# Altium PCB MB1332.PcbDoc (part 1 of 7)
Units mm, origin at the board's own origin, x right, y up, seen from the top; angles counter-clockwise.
Board outline 161 x 75 mm, 6 copper layers (Top Layer, Signal Layer 1, Signal Layer 2, Signal Layer 3, Signal Layer 4, Bottom Layer), stack 1.57 mm thick; 387 components, 358 nets, 1659 pads, 1180 vias.
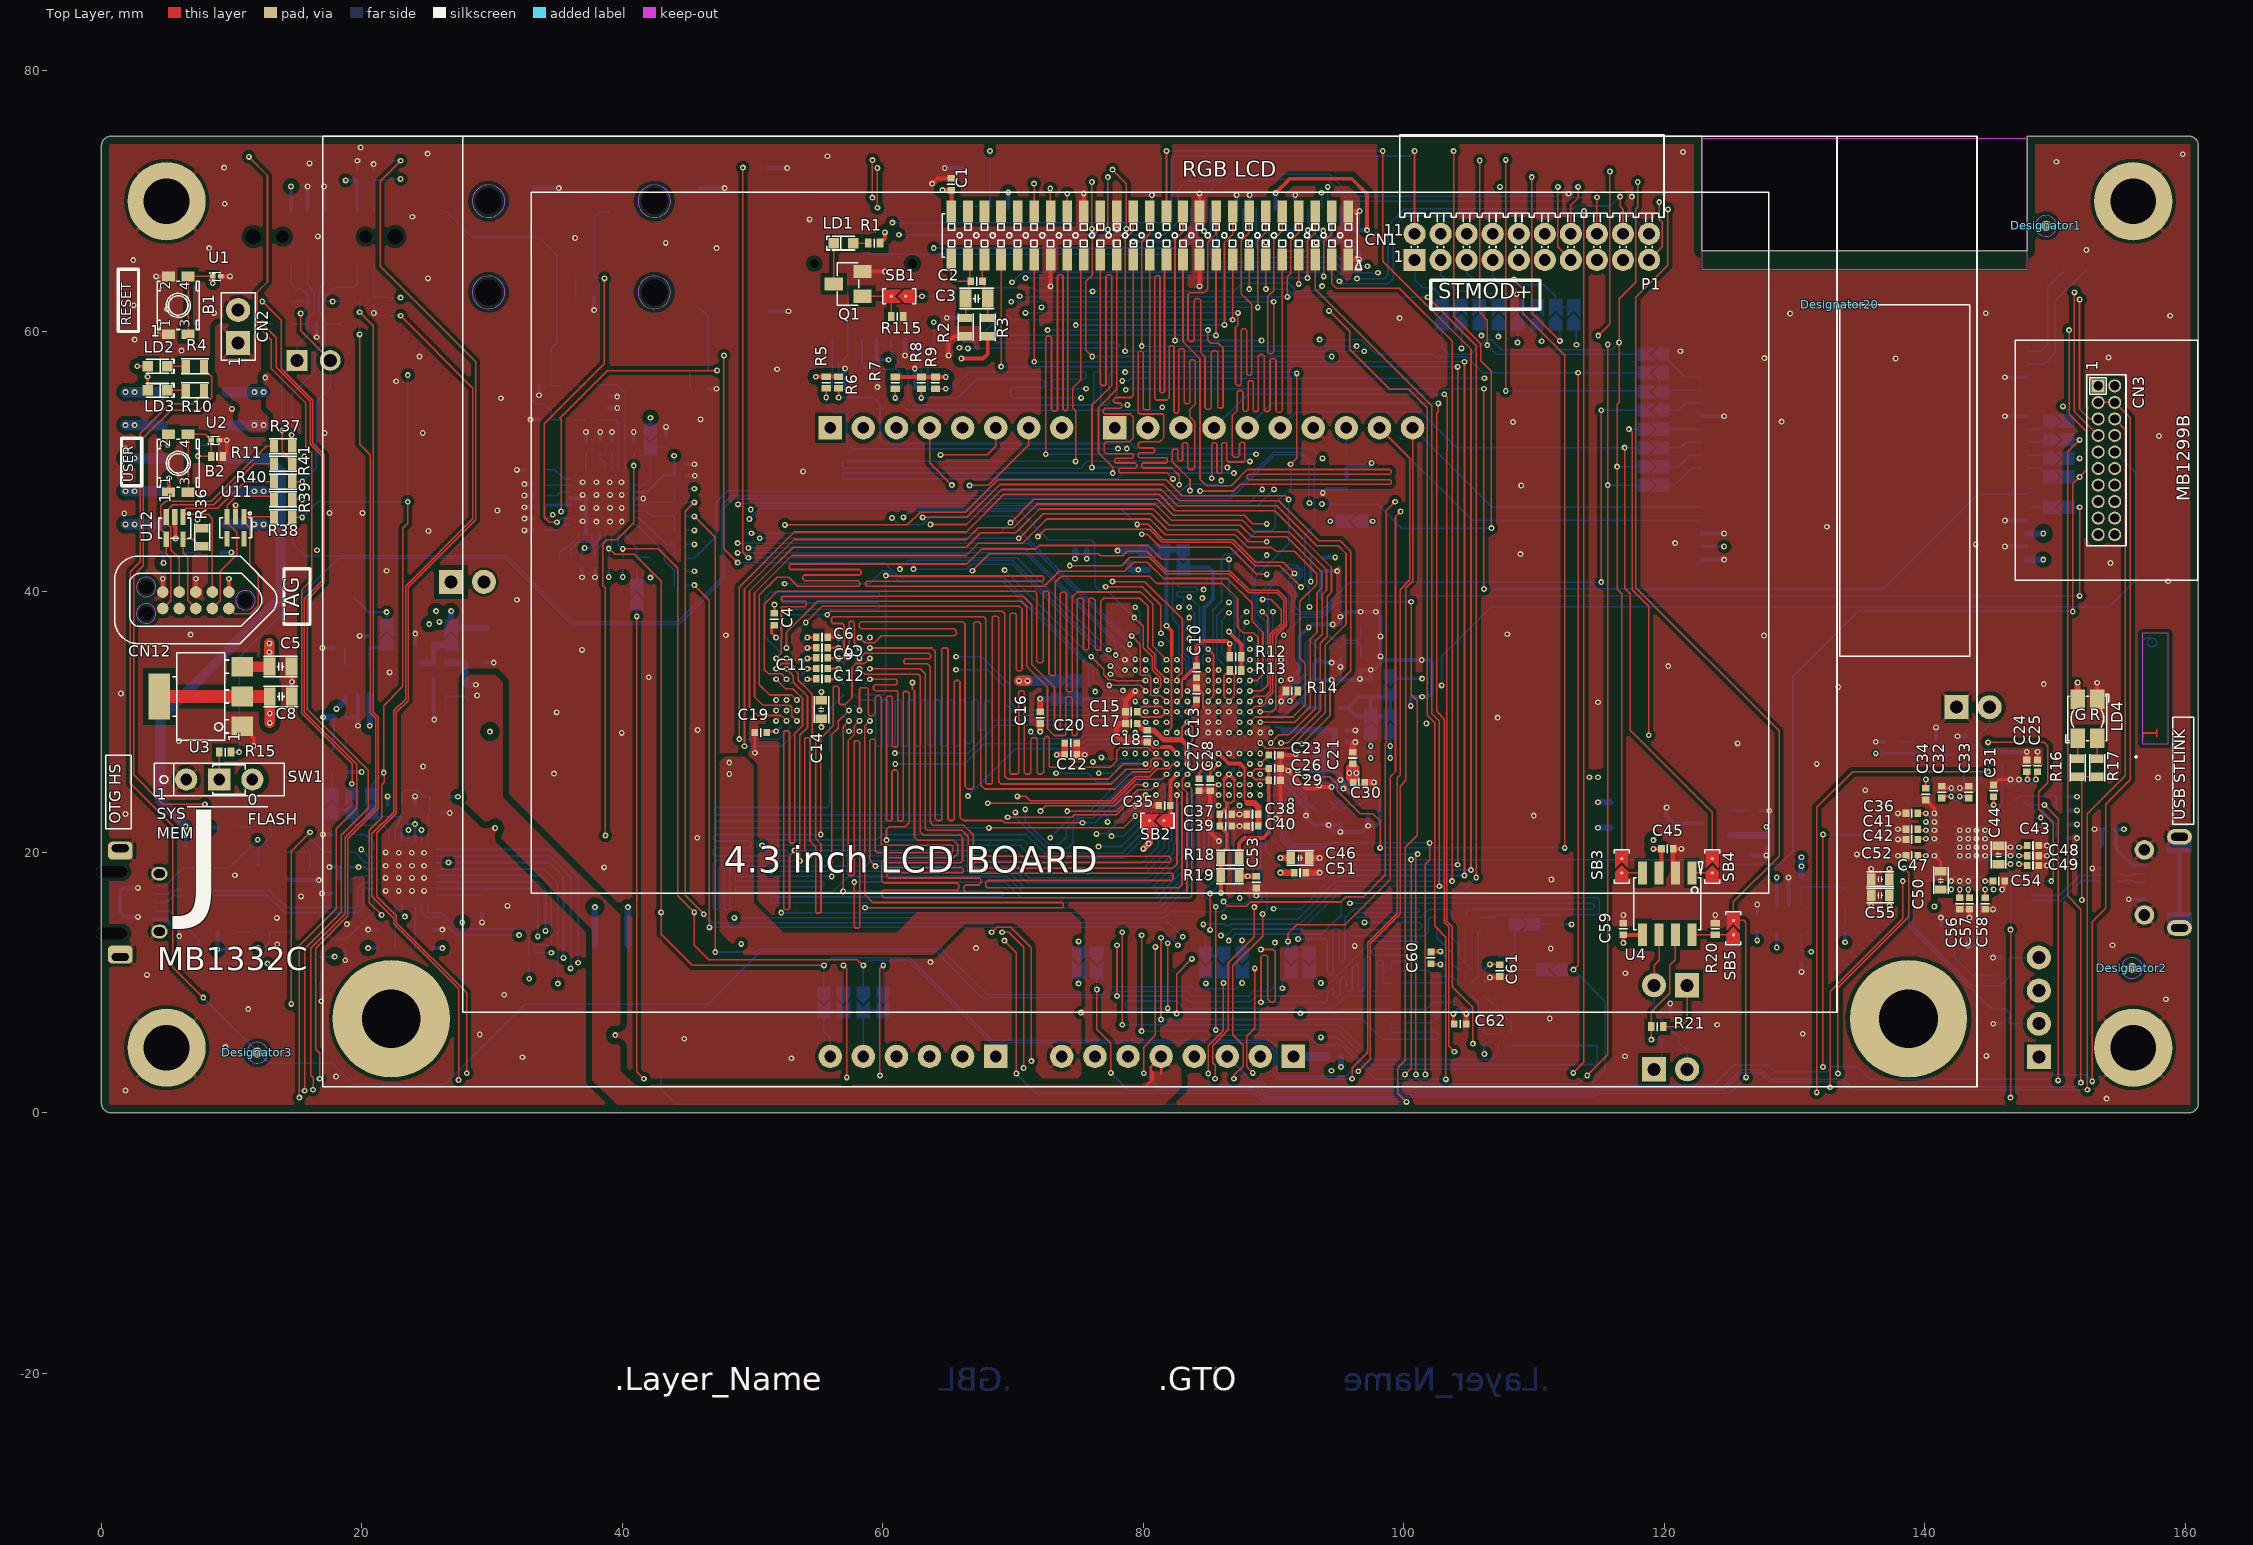
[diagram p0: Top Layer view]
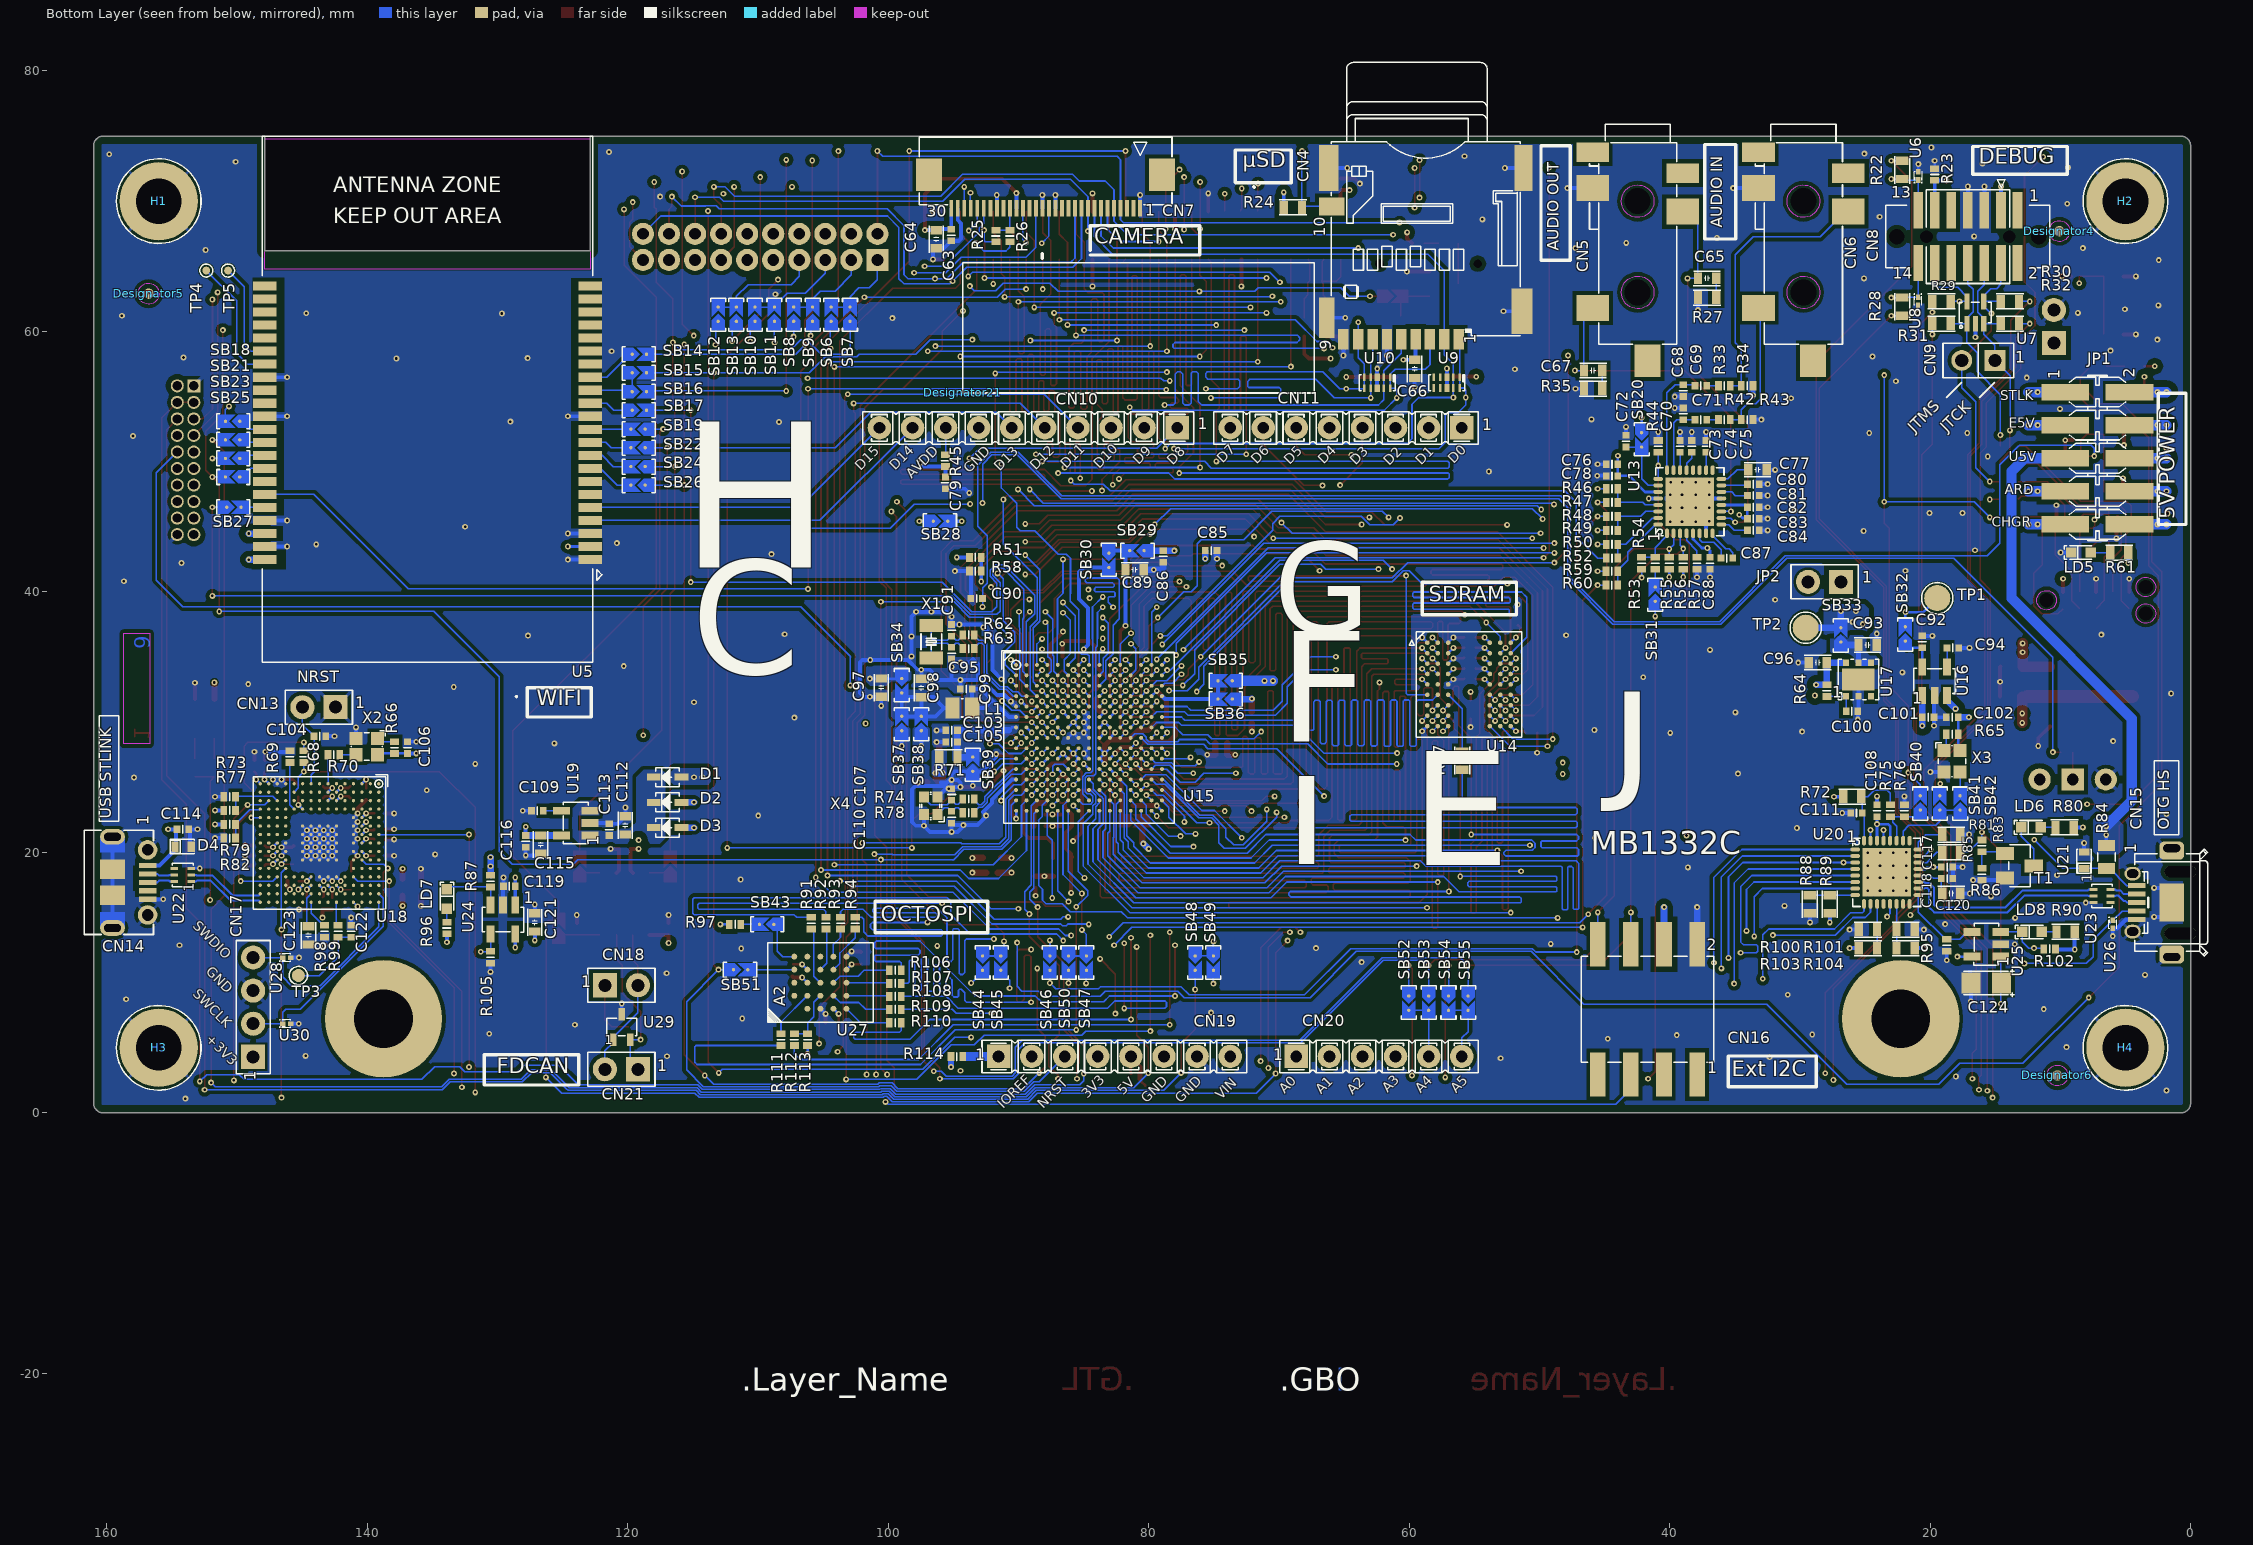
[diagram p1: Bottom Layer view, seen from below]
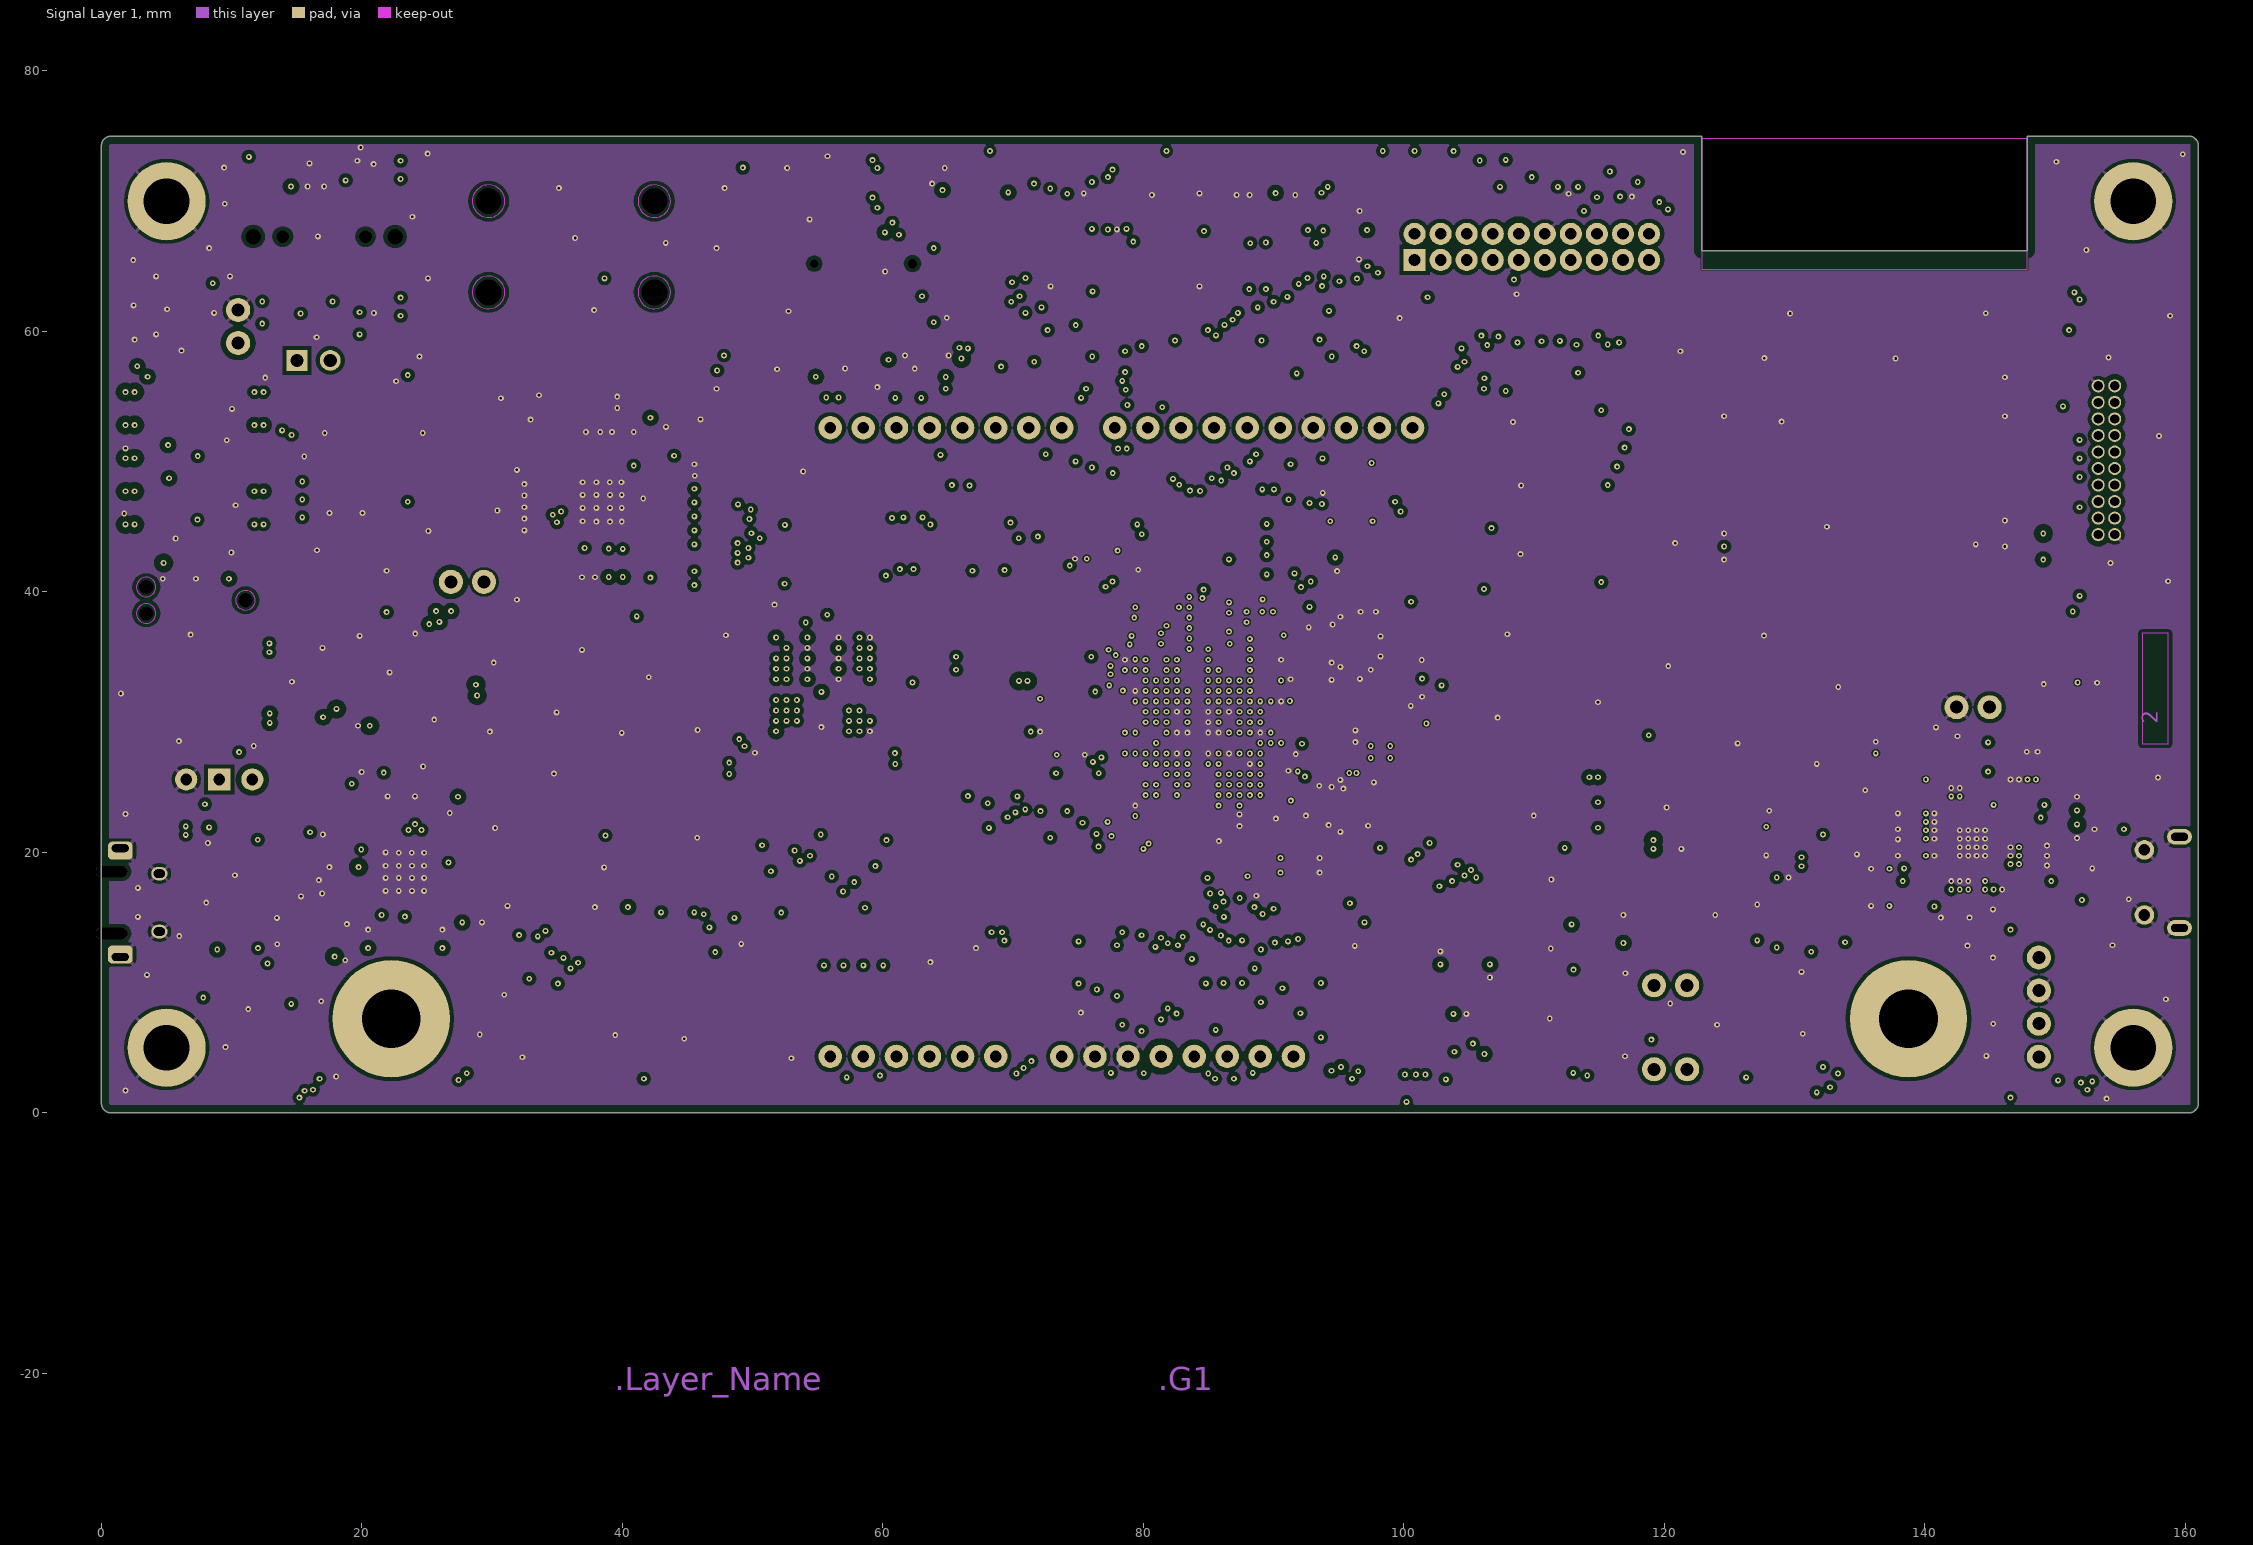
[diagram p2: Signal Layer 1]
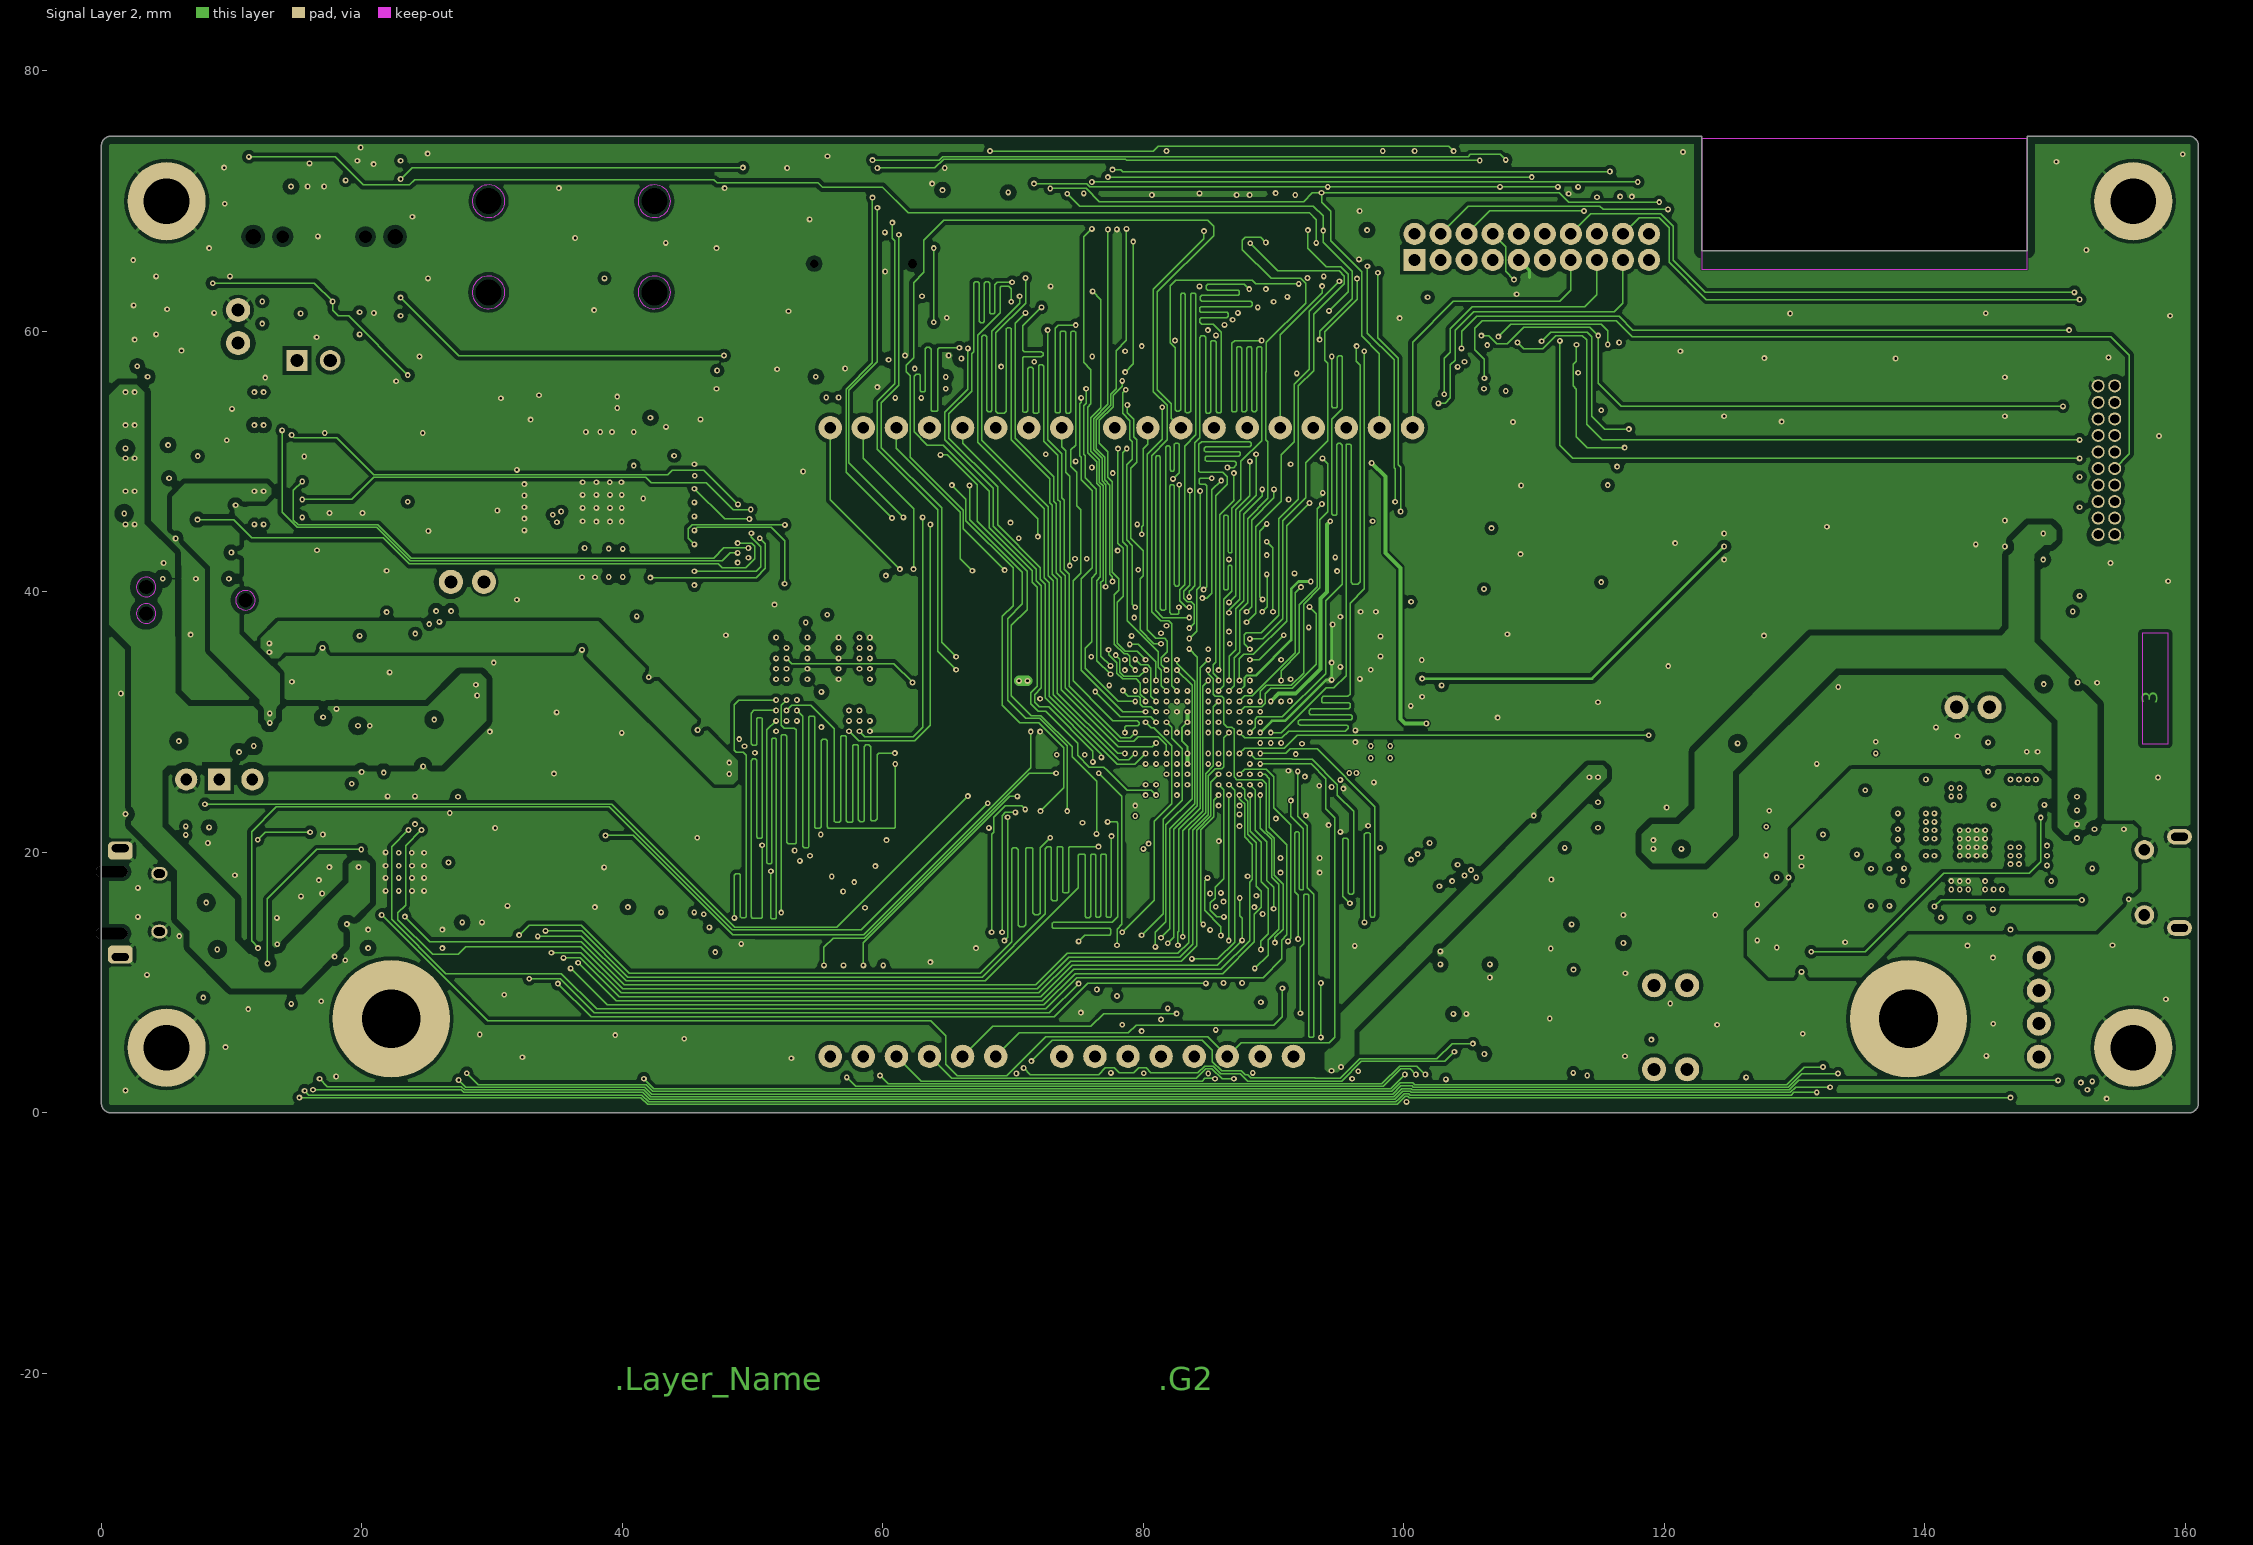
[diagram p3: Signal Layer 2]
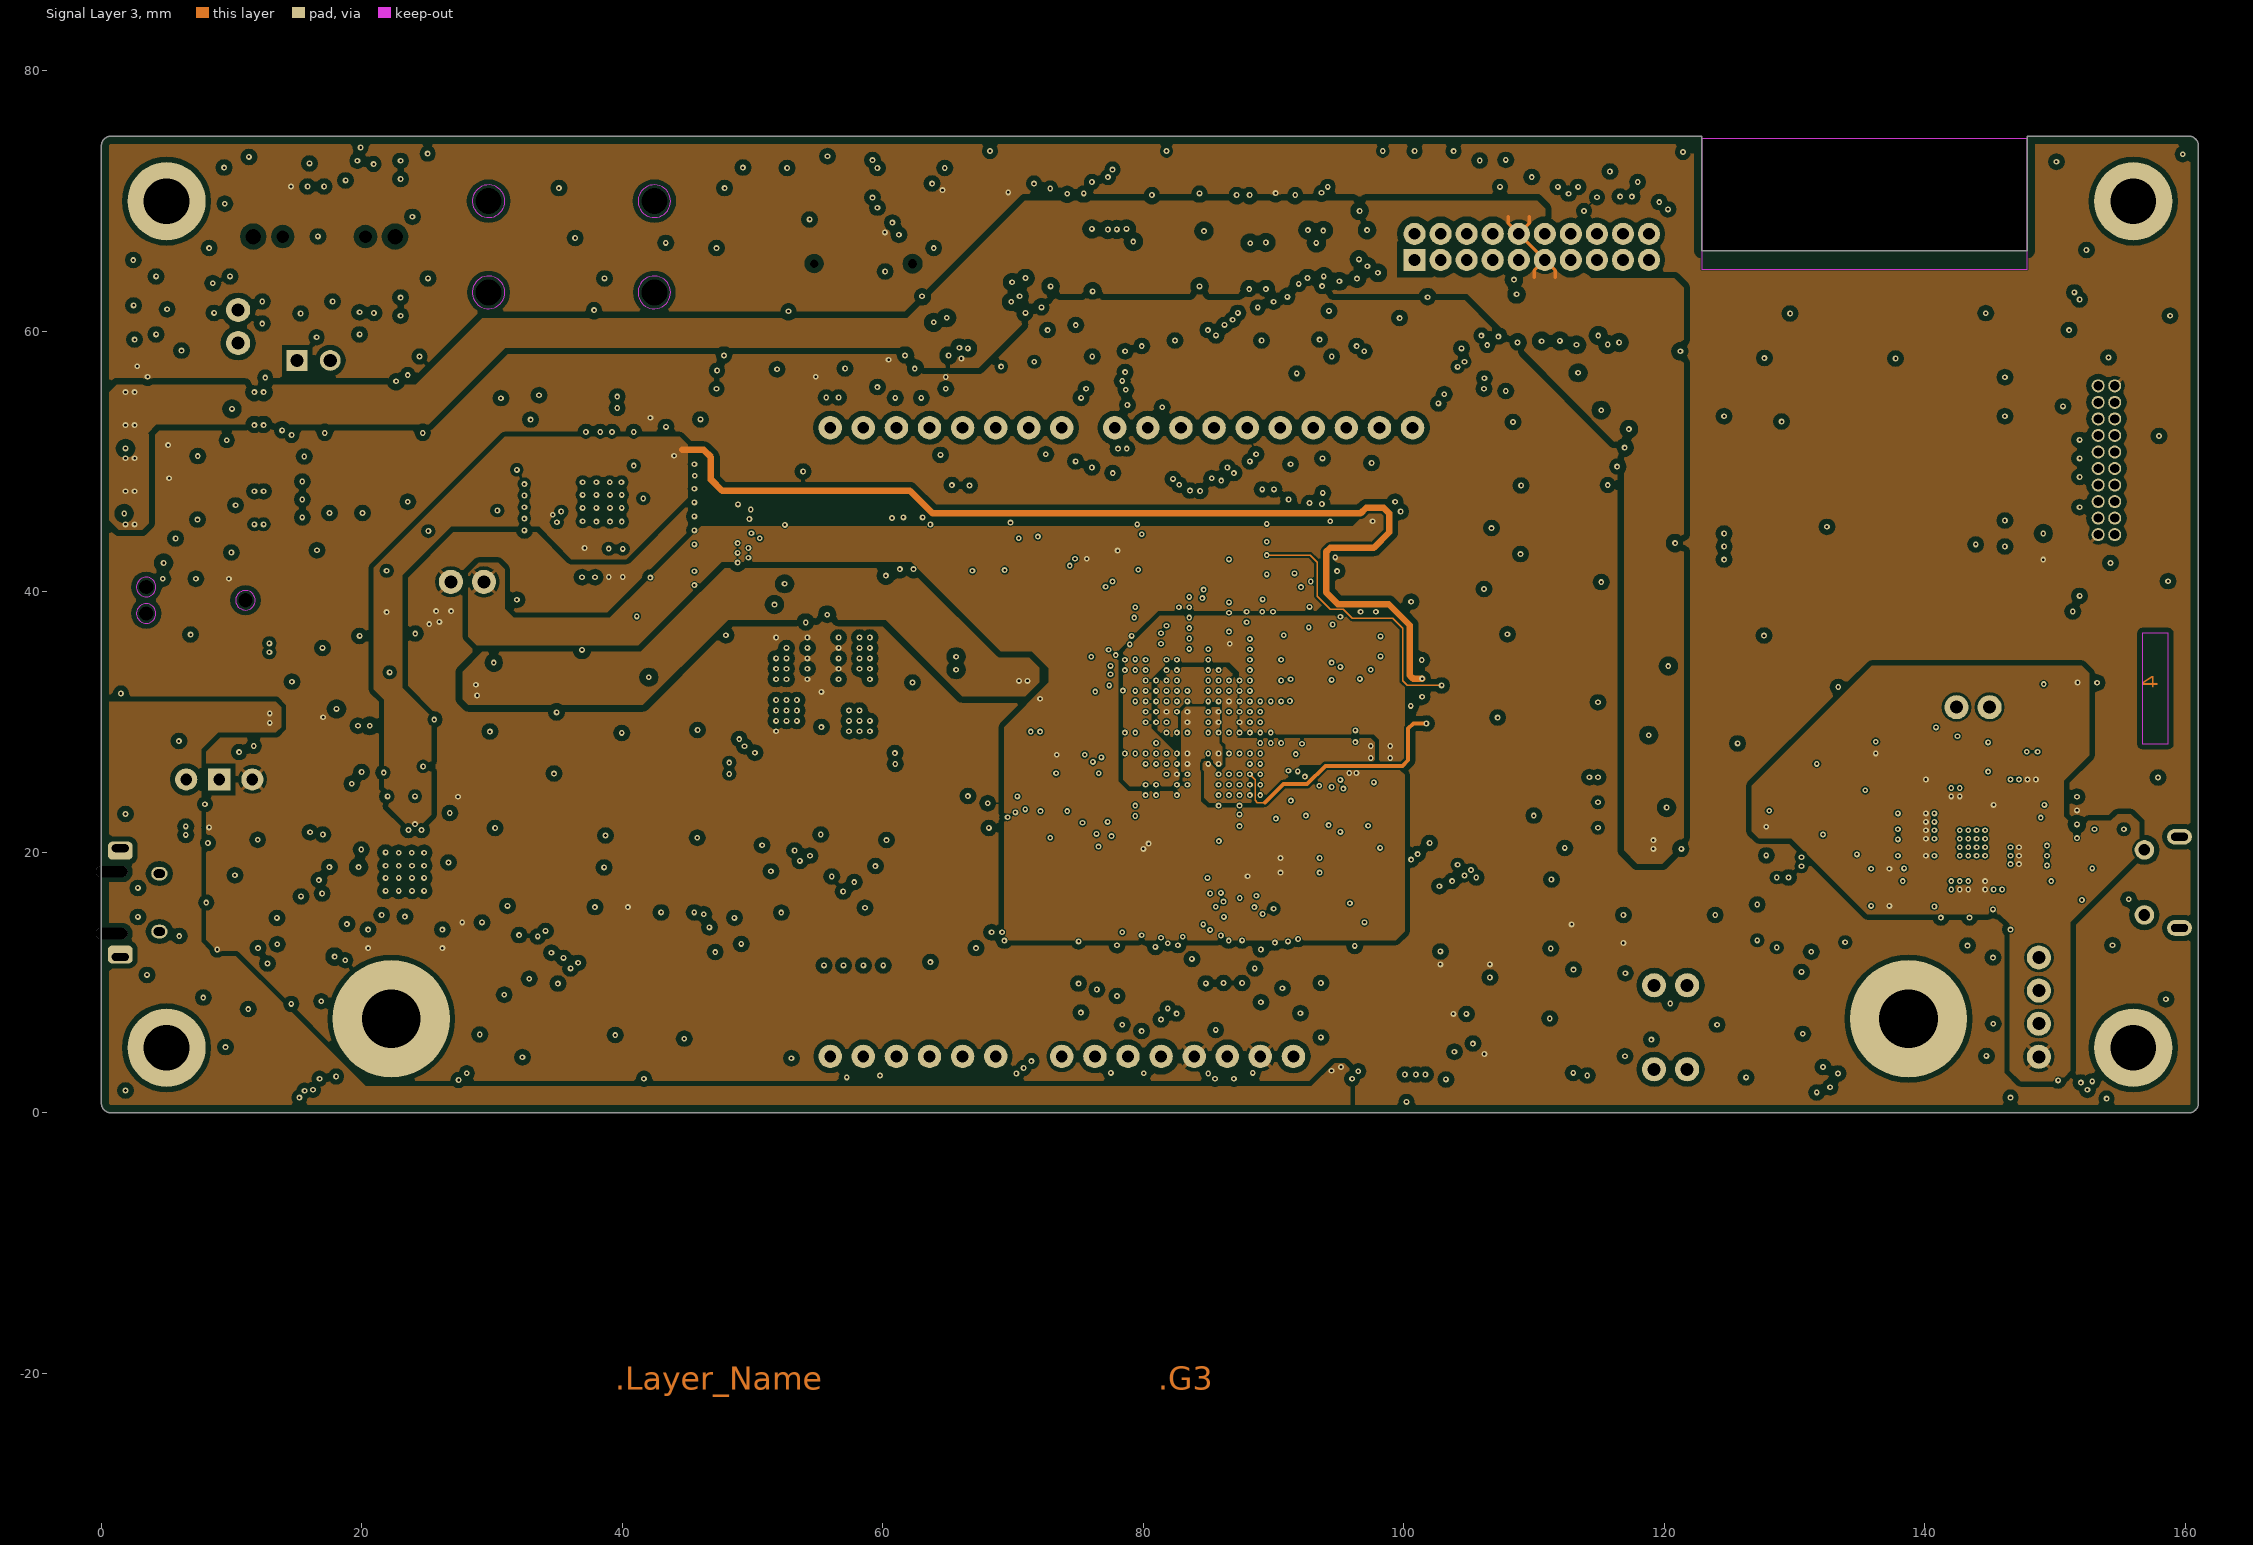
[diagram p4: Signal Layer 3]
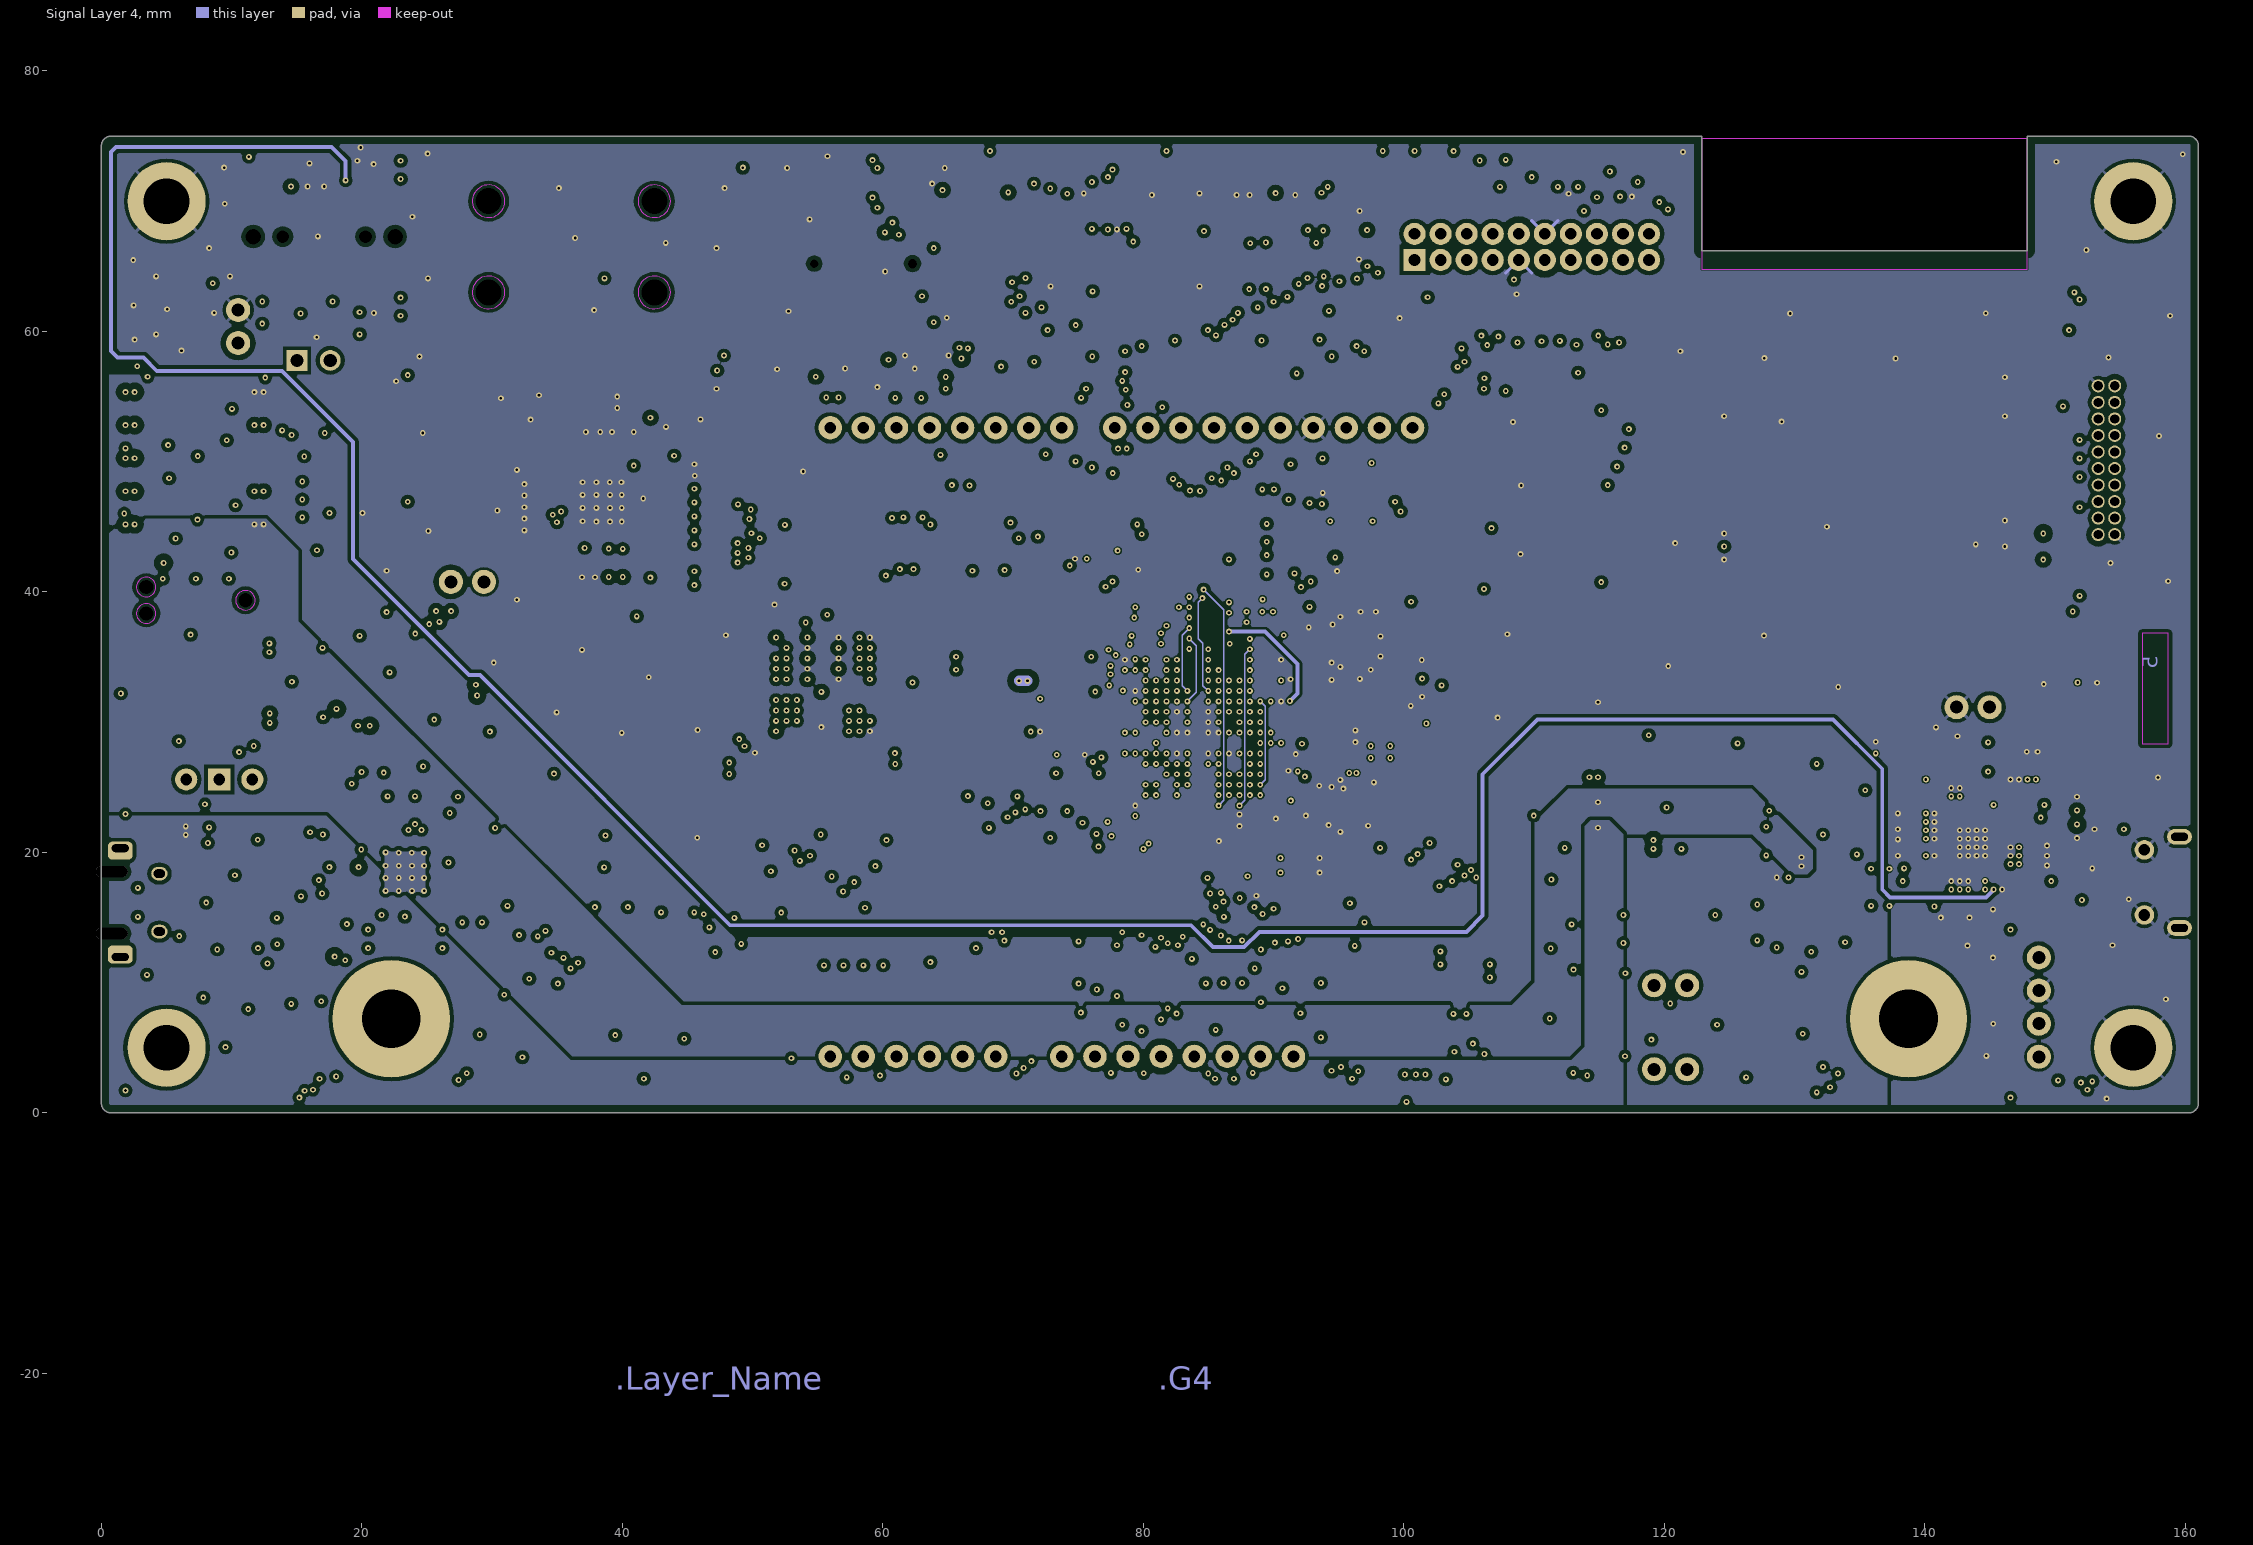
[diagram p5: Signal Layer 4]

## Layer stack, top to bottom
Top Solder: solder mask 0.015, Solder Resist, Dk 3.5
Top Layer: signal copper 0.042
Dielectric 1: prepreg 0.0991, FR-4, Dk 4.2
Signal Layer 1: signal copper 0.0348
Dielectric 2: core 0.1016, Dk 4.2
Signal Layer 2: signal copper 0.0348
Dielectric 3: prepreg 0.9457, Dk 4.2
Signal Layer 3: signal copper 0.0348
Dielectric 4: core 0.1016, Dk 4.2
Signal Layer 4: signal copper 0.0348
Dielectric 5: prepreg 0.0991, Dk 4.2
Bottom Layer: signal copper 0.042
Bottom Solder: solder mask 0.015, Solder Resist, Dk 3.5

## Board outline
0,0.75 0,74.25 cw(c0.75,74.25) 0.75,75 122.861,75 122.861,66.2 147.861,66.2 147.861,75 160.25,75 cw(c160.25,74.25) 161,74.25 161,0.75 cw(c160.25,0.75) 160.25,0 0.75,0 cw(c0.75,0.75)

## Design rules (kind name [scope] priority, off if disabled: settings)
BoardOutlineClearance [All] p1: gap=0.6 ignorepadtopadclearanceinfootprint=FALSE
Clearance Clearance_BGA-U24 [WithinRoom('RoomDefinition') And TouchesRoom('RoomDefinition')] p1: gap=0.1 ignorepadtopadclearanceinfootprint=FALSE except(0: Arc-Hole Track-Hole SMDPad-Hole THPad-Hole Via-Hole Fill-Hole Poly-Hole Region-Hole Text-Hole; 0.15: SMDPad-SMDPad; 0.2: Arc-Fill Arc-Poly Track-Fill Track-Poly SMDPad-THPad SMDPad-Fill SMDPad-Poly THPad-THPad THPad-Fill THPad-Poly Via-Via Via-Fill Fill-Poly; 0.3: Fill-Fill Poly-Poly)
Clearance Clearance_SDRAM_L1 [InNetClass('NC_SDRAM_SINGLE-55R') vs OnLayer('Top Layer')] p2: gap=0.1 ignorepadtopadclearanceinfootprint=FALSE except(0: Arc-Hole Track-Hole SMDPad-Hole THPad-Hole Via-Hole Fill-Hole Poly-Hole Region-Hole Text-Hole; 0.15: SMDPad-SMDPad; 0.2: Arc-Fill Track-Fill SMDPad-THPad SMDPad-Fill THPad-THPad THPad-Fill Via-Via Via-Fill; 0.254: Track-Track; 0.3: Arc-Poly Track-Poly SMDPad-Poly THPad-Poly Via-Poly Fill-Fill Fill-Poly Poly-Poly)
Clearance Clearance_LCD-W127 [InNetClass('NC_LCD_SINGLE-55R_W127u')] p3: gap=0.1 ignorepadtopadclearanceinfootprint=FALSE except(0: Arc-Hole Track-Hole SMDPad-Hole THPad-Hole Via-Hole Fill-Hole Poly-Hole Region-Hole Text-Hole; 0.15: SMDPad-SMDPad; 0.2: Arc-Fill Track-Fill SMDPad-THPad SMDPad-Fill THPad-THPad THPad-Fill Via-Via Via-Fill; 0.254: Track-Track; 0.3: Arc-Poly Track-Poly SMDPad-Poly THPad-Poly Via-Poly Fill-Fill Fill-Poly Poly-Poly)
Clearance Clearance_LCD_L1 [InNetClass('NC_LCD_SINGLE-55R') vs OnLayer('Top Layer')] p4: gap=0.1 ignorepadtopadclearanceinfootprint=FALSE except(0: Arc-Hole Track-Hole SMDPad-Hole THPad-Hole Via-Hole Fill-Hole Poly-Hole Region-Hole Text-Hole; 0.15: SMDPad-SMDPad; 0.2: Arc-Fill Track-Fill SMDPad-THPad SMDPad-Fill THPad-THPad THPad-Fill Via-Via Via-Fill; 0.254: Track-Track; 0.3: Arc-Poly Track-Poly SMDPad-Poly THPad-Poly Via-Poly Fill-Fill Fill-Poly Poly-Poly)
Clearance Clearance_OCTO-SPI_L1 [InNetClass('NC_OCTO-SPI_SINGLE-55R') vs OnLayer('Top Layer')] p5: gap=0.1 ignorepadtopadclearanceinfootprint=FALSE except(0: Arc-Hole Track-Hole SMDPad-Hole THPad-Hole Via-Hole Fill-Hole Poly-Hole Region-Hole Text-Hole; 0.15: SMDPad-SMDPad; 0.2: Arc-Fill Track-Fill SMDPad-THPad SMDPad-Fill THPad-THPad THPad-Fill Via-Via Via-Fill; 0.254: Track-Track; 0.3: Arc-Poly Track-Poly SMDPad-Poly THPad-Poly Via-Poly Fill-Fill Fill-Poly Poly-Poly)
Clearance Clearance_SD-CARD_L1 [InNetClass('NC_SD-CARD_SINGLE-55R') vs OnLayer('Top Layer')] p6: gap=0.1 ignorepadtopadclearanceinfootprint=FALSE except(0: Arc-Hole Track-Hole SMDPad-Hole THPad-Hole Via-Hole Fill-Hole Poly-Hole Region-Hole Text-Hole; 0.15: SMDPad-SMDPad; 0.2: Arc-Fill Track-Fill SMDPad-THPad SMDPad-Fill THPad-THPad THPad-Fill Via-Via Via-Fill; 0.254: Track-Track; 0.3: Arc-Poly Track-Poly SMDPad-Poly THPad-Poly Via-Poly Fill-Fill Fill-Poly Poly-Poly)
Clearance Clearance_CAMERA_L1 [InNetClass('NC_CAMERA_SINGLE-55R') vs OnLayer('Top Layer')] p7: gap=0.1 ignorepadtopadclearanceinfootprint=FALSE except(0: Arc-Hole Track-Hole SMDPad-Hole THPad-Hole Via-Hole Fill-Hole Poly-Hole Region-Hole Text-Hole; 0.15: SMDPad-SMDPad; 0.2: Arc-Fill Track-Fill SMDPad-THPad SMDPad-Fill THPad-THPad THPad-Fill Via-Via Via-Fill; 0.254: Track-Track; 0.3: Arc-Poly Track-Poly SMDPad-Poly THPad-Poly Via-Poly Fill-Fill Fill-Poly Poly-Poly)
Clearance Clearance_ULPI_L1 [InNetClass('NC_ULPI_SINGLE-55R') vs OnLayer('Top Layer')] p8: gap=0.1 ignorepadtopadclearanceinfootprint=FALSE except(0: Arc-Hole Track-Hole SMDPad-Hole THPad-Hole Via-Hole Fill-Hole Poly-Hole Region-Hole Text-Hole; 0.15: SMDPad-SMDPad; 0.2: Arc-Fill Track-Fill SMDPad-THPad SMDPad-Fill THPad-THPad THPad-Fill Via-Via Via-Fill; 0.254: Track-Track; 0.3: Arc-Poly Track-Poly SMDPad-Poly THPad-Poly Via-Poly Fill-Fill Fill-Poly Poly-Poly)
Clearance Clearance_SDRAM_L6 [InNetClass('NC_SDRAM_SINGLE-55R') vs OnLayer('Bottom Layer')] p9: gap=0.1 ignorepadtopadclearanceinfootprint=FALSE except(0: Arc-Hole Track-Hole SMDPad-Hole THPad-Hole Via-Hole Fill-Hole Poly-Hole Region-Hole Text-Hole; 0.15: SMDPad-SMDPad; 0.2: Arc-Fill Track-Fill SMDPad-THPad SMDPad-Fill THPad-THPad THPad-Fill Via-Via Via-Fill; 0.254: Track-Track; 0.3: Arc-Poly Track-Poly SMDPad-Poly THPad-Poly Via-Poly Fill-Fill Fill-Poly Poly-Poly)
Clearance Clearance_LCD_L6 [InNetClass('NC_LCD_SINGLE-55R') vs OnLayer('Bottom Layer')] p10: gap=0.1 ignorepadtopadclearanceinfootprint=FALSE except(0: Arc-Hole Track-Hole SMDPad-Hole THPad-Hole Via-Hole Fill-Hole Poly-Hole Region-Hole Text-Hole; 0.15: SMDPad-SMDPad; 0.2: Arc-Fill Track-Fill SMDPad-THPad SMDPad-Fill THPad-THPad THPad-Fill Via-Via Via-Fill; 0.254: Track-Track; 0.3: Arc-Poly Track-Poly SMDPad-Poly THPad-Poly Via-Poly Fill-Fill Fill-Poly Poly-Poly)
Clearance Clearance_OCTO-SPI_L6 [InNetClass('NC_OCTO-SPI_SINGLE-55R') vs OnLayer('Bottom Layer')] p11: gap=0.1 ignorepadtopadclearanceinfootprint=FALSE except(0: Arc-Hole Track-Hole SMDPad-Hole THPad-Hole Via-Hole Fill-Hole Poly-Hole Region-Hole Text-Hole; 0.15: SMDPad-SMDPad; 0.2: Arc-Fill Track-Fill SMDPad-THPad SMDPad-Fill THPad-THPad THPad-Fill Via-Via Via-Fill; 0.254: Track-Track; 0.3: Arc-Poly Track-Poly SMDPad-Poly THPad-Poly Via-Poly Fill-Fill Fill-Poly Poly-Poly)
Clearance Clearance_SD-CARD_L6 [InNetClass('NC_SD-CARD_SINGLE-55R') vs OnLayer('Bottom Layer')] p12: gap=0.1 ignorepadtopadclearanceinfootprint=FALSE except(0: Arc-Hole Track-Hole SMDPad-Hole THPad-Hole Via-Hole Fill-Hole Poly-Hole Region-Hole Text-Hole; 0.15: SMDPad-SMDPad; 0.2: Arc-Fill Track-Fill SMDPad-THPad SMDPad-Fill THPad-THPad THPad-Fill Via-Via Via-Fill; 0.254: Track-Track; 0.3: Arc-Poly Track-Poly SMDPad-Poly THPad-Poly Via-Poly Fill-Fill Fill-Poly Poly-Poly)
Clearance Clearance_CAMERA_L6 [InNetClass('NC_CAMERA_SINGLE-55R') vs OnLayer('Bottom Layer')] p13: gap=0.1 ignorepadtopadclearanceinfootprint=FALSE except(0: Arc-Hole Track-Hole SMDPad-Hole THPad-Hole Via-Hole Fill-Hole Poly-Hole Region-Hole Text-Hole; 0.15: SMDPad-SMDPad; 0.2: Arc-Fill Track-Fill SMDPad-THPad SMDPad-Fill THPad-THPad THPad-Fill Via-Via Via-Fill; 0.254: Track-Track; 0.3: Arc-Poly Track-Poly SMDPad-Poly THPad-Poly Via-Poly Fill-Fill Fill-Poly Poly-Poly)
Clearance Clearance_ULPI_L6 [InNetClass('NC_ULPI_SINGLE-55R') vs OnLayer('Bottom Layer')] p14: gap=0.1 ignorepadtopadclearanceinfootprint=FALSE except(0: Arc-Hole Track-Hole SMDPad-Hole THPad-Hole Via-Hole Fill-Hole Poly-Hole Region-Hole Text-Hole; 0.15: SMDPad-SMDPad; 0.2: Arc-Fill Track-Fill SMDPad-THPad SMDPad-Fill THPad-THPad THPad-Fill Via-Via Via-Fill; 0.254: Track-Track; 0.3: Arc-Poly Track-Poly SMDPad-Poly THPad-Poly Via-Poly Fill-Fill Fill-Poly Poly-Poly)
Clearance Clearance_SDRAM_L3 [InNetClass('NC_SDRAM_SINGLE-55R') vs OnLayer('Signal Layer 2')] p15: gap=0.1 ignorepadtopadclearanceinfootprint=FALSE except(0: Arc-Hole Track-Hole SMDPad-Hole THPad-Hole Via-Hole Fill-Hole Poly-Hole Region-Hole Text-Hole; 0.15: SMDPad-SMDPad; 0.2: Arc-Fill Track-Fill SMDPad-THPad SMDPad-Fill THPad-THPad THPad-Fill Via-Via Via-Fill; 0.204: Track-Track; 0.3: Arc-Poly Track-Poly SMDPad-Poly THPad-Poly Via-Poly Fill-Fill Fill-Poly Poly-Poly)
Clearance Clearance_LCD_L3 [InNetClass('NC_LCD_SINGLE-55R') vs OnLayer('Signal Layer 2')] p16: gap=0.1 ignorepadtopadclearanceinfootprint=FALSE except(0: Arc-Hole Track-Hole SMDPad-Hole THPad-Hole Via-Hole Fill-Hole Poly-Hole Region-Hole Text-Hole; 0.15: SMDPad-SMDPad; 0.2: Arc-Fill Track-Fill SMDPad-THPad SMDPad-Fill THPad-THPad THPad-Fill Via-Via Via-Fill; 0.204: Track-Track; 0.3: Arc-Poly Track-Poly SMDPad-Poly THPad-Poly Via-Poly Fill-Fill Fill-Poly Poly-Poly)
Clearance Clearance_OCTO-SPI_L3 [InNetClass('NC_OCTO-SPI_SINGLE-55R') vs OnLayer('Signal Layer 2')] p17: gap=0.1 ignorepadtopadclearanceinfootprint=FALSE except(0: Arc-Hole Track-Hole SMDPad-Hole THPad-Hole Via-Hole Fill-Hole Poly-Hole Region-Hole Text-Hole; 0.15: SMDPad-SMDPad; 0.2: Arc-Fill Track-Fill SMDPad-THPad SMDPad-Fill THPad-THPad THPad-Fill Via-Via Via-Fill; 0.204: Track-Track; 0.3: Arc-Poly Track-Poly SMDPad-Poly THPad-Poly Via-Poly Fill-Fill Fill-Poly Poly-Poly)
Clearance Clearance_SD-CARD_L3 [InNetClass('NC_SD-CARD_SINGLE-55R') vs OnLayer('Signal Layer 2')] p18: gap=0.1 ignorepadtopadclearanceinfootprint=FALSE except(0: Arc-Hole Track-Hole SMDPad-Hole THPad-Hole Via-Hole Fill-Hole Poly-Hole Region-Hole Text-Hole; 0.15: SMDPad-SMDPad; 0.2: Arc-Fill Track-Fill SMDPad-THPad SMDPad-Fill THPad-THPad THPad-Fill Via-Via Via-Fill; 0.204: Track-Track; 0.3: Arc-Poly Track-Poly SMDPad-Poly THPad-Poly Via-Poly Fill-Fill Fill-Poly Poly-Poly)
Clearance Clearance_CAMERA_L3 [InNetClass('NC_CAMERA_SINGLE-55R') vs OnLayer('Signal Layer 2')] p19: gap=0.1 ignorepadtopadclearanceinfootprint=FALSE except(0: Arc-Hole Track-Hole SMDPad-Hole THPad-Hole Via-Hole Fill-Hole Poly-Hole Region-Hole Text-Hole; 0.15: SMDPad-SMDPad; 0.2: Arc-Fill Track-Fill SMDPad-THPad SMDPad-Fill THPad-THPad THPad-Fill Via-Via Via-Fill; 0.204: Track-Track; 0.3: Arc-Poly Track-Poly SMDPad-Poly THPad-Poly Via-Poly Fill-Fill Fill-Poly Poly-Poly)
Clearance Clearance_ULPI_L3 [InNetClass('NC_ULPI_SINGLE-55R') vs OnLayer('Signal Layer 2')] p20: gap=0.1 ignorepadtopadclearanceinfootprint=FALSE except(0: Arc-Hole Track-Hole SMDPad-Hole THPad-Hole Via-Hole Fill-Hole Poly-Hole Region-Hole Text-Hole; 0.15: SMDPad-SMDPad; 0.2: Arc-Fill Track-Fill SMDPad-THPad SMDPad-Fill THPad-THPad THPad-Fill Via-Via Via-Fill; 0.204: Track-Track; 0.3: Arc-Poly Track-Poly SMDPad-Poly THPad-Poly Via-Poly Fill-Fill Fill-Poly Poly-Poly)
Clearance Clearance_USB_HS_CN18__90R [InNetClass('NC_USB_HS_CN18__90R')] p21: gap=0.1 ignorepadtopadclearanceinfootprint=FALSE except(0: Arc-Hole Track-Hole SMDPad-Hole THPad-Hole Via-Hole Fill-Hole Poly-Hole Region-Hole Text-Hole; 0.15: SMDPad-SMDPad; 0.2: Arc-Fill Track-Fill SMDPad-THPad SMDPad-Fill THPad-THPad THPad-Fill Via-Via Via-Fill; 0.3: Fill-Fill; 0.465: Arc-Poly Track-Poly SMDPad-Poly THPad-Poly Via-Poly Fill-Poly Poly-Poly)
Clearance Clearance_USB_DEV_HS_CN__90R [InNetClass('NC_USB_DEV_HS_CN__90R')] p22: gap=0.1 ignorepadtopadclearanceinfootprint=FALSE except(0: Arc-Hole Track-Hole SMDPad-Hole THPad-Hole Via-Hole Fill-Hole Poly-Hole Region-Hole Text-Hole; 0.15: SMDPad-SMDPad; 0.2: Arc-Fill Track-Fill SMDPad-THPad SMDPad-Fill THPad-THPad THPad-Fill Via-Via Via-Fill; 0.3: Fill-Fill; 0.465: Arc-Poly Track-Poly SMDPad-Poly THPad-Poly Via-Poly Fill-Poly Poly-Poly)
Clearance Clearance_USB_HS__90R [InNetClass('NC_USB_HS__90R')] p23: gap=0.1 ignorepadtopadclearanceinfootprint=FALSE except(0: Arc-Hole Track-Hole SMDPad-Hole THPad-Hole Via-Hole Fill-Hole Poly-Hole Region-Hole Text-Hole; 0.15: SMDPad-SMDPad; 0.2: Arc-Fill Track-Fill SMDPad-THPad SMDPad-Fill THPad-THPad THPad-Fill Via-Via Via-Fill; 0.3: Fill-Fill; 0.465: Arc-Poly Track-Poly SMDPad-Poly THPad-Poly Via-Poly Fill-Poly Poly-Poly)
Clearance Clearance_USB_DEV_HS__90R [InNetClass('NC_USB_DEV_HS__90R')] p24: gap=0.1 ignorepadtopadclearanceinfootprint=FALSE except(0: Arc-Hole Track-Hole SMDPad-Hole THPad-Hole Via-Hole Fill-Hole Poly-Hole Region-Hole Text-Hole; 0.15: SMDPad-SMDPad; 0.2: Arc-Fill Track-Fill SMDPad-THPad SMDPad-Fill THPad-THPad THPad-Fill Via-Via Via-Fill; 0.3: Fill-Fill; 0.465: Arc-Poly Track-Poly SMDPad-Poly THPad-Poly Via-Poly Fill-Poly Poly-Poly)
Clearance Clearance_ALIMS_W2 [InNetClass('NC_ALIMS_W2mm')] p25: gap=0.1 ignorepadtopadclearanceinfootprint=FALSE except(0: Arc-Hole Track-Hole SMDPad-Hole THPad-Hole Via-Hole Fill-Hole Poly-Hole Region-Hole Text-Hole; 0.15: SMDPad-SMDPad; 0.2: Arc-Fill Track-Fill SMDPad-THPad SMDPad-Fill SMDPad-Poly THPad-THPad THPad-Fill Via-Via Via-Fill; 0.3: Fill-Fill; 0.5: Arc-Poly Track-Poly THPad-Poly Via-Poly Fill-Poly Poly-Poly)
Clearance Clearance_ALIMS_W1 [InNetClass('NC_ALIMS_W1mm')] p26: gap=0.1 ignorepadtopadclearanceinfootprint=FALSE except(0: Arc-Hole Track-Hole SMDPad-Hole THPad-Hole Via-Hole Fill-Hole Poly-Hole Region-Hole Text-Hole; 0.15: SMDPad-SMDPad; 0.2: Arc-Fill Track-Fill SMDPad-THPad SMDPad-Fill THPad-THPad THPad-Fill Via-Via Via-Fill; 0.3: Fill-Fill; 0.4: Arc-Poly Track-Poly SMDPad-Poly THPad-Poly Via-Poly Fill-Poly Poly-Poly)
Clearance Clearance_ALIMS_W0.8 [InNetClass('NC_ALIMS_W0.8mm')] p27: gap=0.1 ignorepadtopadclearanceinfootprint=FALSE except(0: Arc-Hole Track-Hole SMDPad-Hole THPad-Hole Via-Hole Fill-Hole Poly-Hole Region-Hole Text-Hole; 0.15: SMDPad-SMDPad; 0.2: Arc-Fill Track-Fill SMDPad-THPad SMDPad-Fill THPad-THPad THPad-Fill Via-Via Via-Fill; 0.3: Arc-Poly Track-Poly SMDPad-Poly THPad-Poly Via-Poly Fill-Fill Fill-Poly Poly-Poly)
Clearance Clearance_ALIMS_W1.5 [InNetClass('NC_ALIMS_W1.5mm')] p28: gap=0.1 ignorepadtopadclearanceinfootprint=FALSE except(0: Arc-Hole Track-Hole SMDPad-Hole THPad-Hole Via-Hole Fill-Hole Poly-Hole Region-Hole Text-Hole; 0.15: SMDPad-SMDPad; 0.2: Arc-Fill Track-Fill SMDPad-THPad SMDPad-Fill THPad-THPad THPad-Fill Via-Via Via-Fill; 0.3: Fill-Fill; 0.4: Arc-Poly Track-Poly SMDPad-Poly THPad-Poly Via-Poly Fill-Poly Poly-Poly)
Clearance Clearance_ALIMS_W0.5 [InNetClass('NC_ALIMS_W0.5mm')] p29: gap=0.1 ignorepadtopadclearanceinfootprint=FALSE except(0: Arc-Hole Track-Hole SMDPad-Hole THPad-Hole Via-Hole Fill-Hole Poly-Hole Region-Hole Text-Hole; 0.15: SMDPad-SMDPad; 0.2: Arc-Fill Arc-Poly Track-Fill Track-Poly SMDPad-THPad SMDPad-Fill SMDPad-Poly THPad-THPad THPad-Fill THPad-Poly Via-Via Via-Fill Fill-Poly Poly-Poly; 0.3: Fill-Fill)
Clearance Clearance_ALIMS_W0.2 [InNetClass('NC_ALIMS_W0.2mm')] p30: gap=0.1 ignorepadtopadclearanceinfootprint=FALSE except(0: Arc-Hole Track-Hole SMDPad-Hole THPad-Hole Via-Hole Fill-Hole Poly-Hole Region-Hole Text-Hole; 0.15: SMDPad-SMDPad; 0.2: Arc-Fill Track-Fill SMDPad-THPad SMDPad-Fill THPad-THPad THPad-Fill Via-Via Via-Fill; 0.3: Arc-Poly Track-Poly SMDPad-Poly THPad-Poly Via-Poly Fill-Fill Fill-Poly Poly-Poly)
Clearance Clearance_ALIMS_DEFAULT_W0.3 [InNetClass('NC_ALIMS_DEFAULT_W0.3mm')] p31: gap=0.1 ignorepadtopadclearanceinfootprint=FALSE except(0: Arc-Hole Track-Hole SMDPad-Hole THPad-Hole Via-Hole Fill-Hole Poly-Hole Region-Hole Text-Hole; 0.15: SMDPad-SMDPad; 0.2: Arc-Fill Arc-Poly Track-Fill Track-Poly SMDPad-THPad SMDPad-Fill SMDPad-Poly THPad-THPad THPad-Fill THPad-Poly Via-Via Via-Fill Fill-Poly Poly-Poly; 0.3: Fill-Fill)
Clearance Clearance_GND [InNetClass('NC_GND')] p32: gap=0.1 ignorepadtopadclearanceinfootprint=FALSE except(0: Arc-Hole Track-Hole SMDPad-Hole THPad-Hole Via-Hole Fill-Hole Poly-Hole Region-Hole Text-Hole; 0.15: SMDPad-SMDPad; 0.2: Arc-Fill Track-Fill SMDPad-THPad SMDPad-Fill THPad-THPad THPad-Fill Via-Via Via-Fill; 0.3: Arc-Poly Track-Poly SMDPad-Poly THPad-Poly Via-Poly Fill-Fill Fill-Poly Poly-Poly)
Clearance Clearance_Default [All] p33: gap=0.1 ignorepadtopadclearanceinfootprint=FALSE except(0: Arc-Hole Track-Hole SMDPad-Hole THPad-Hole Via-Hole Fill-Hole Poly-Hole Region-Hole Text-Hole; 0.15: SMDPad-SMDPad; 0.2: Arc-Fill Arc-Poly Track-Fill Track-Poly SMDPad-THPad SMDPad-Fill SMDPad-Poly THPad-THPad THPad-Fill THPad-Poly Via-Via Via-Fill Via-Poly Fill-Poly; 0.3: Fill-Fill Poly-Poly)
ComponentClearance [All] p1 off: gap=0.025 collisioncheckmode=3 verticalgap=0 showdistances=FALSE
DiffPairsRouting DiffPairs_USB_HS_CN18__90R [InDifferentialPairClass('PC_USB_DEV_HS_CN18_DIFF-90R')] p1: maxlimit=0.251 minlimit=0.226 mostfreqgap=0.251 toplayer_maxgap=0.226 toplayer_prefgap=0.226 toplayer_minwidth=0.155 toplayer_maxwidth=0.155 toplayer_prefwidth=0.155 midlayer1_maxgap=0.226 midlayer1_prefgap=0.226 midlayer1_minwidth=0.155 midlayer1_maxwidth=0.155 midlayer1_prefwidth=0.155 midlayer2_mingap=0.251 midlayer2_minwidth=0.13 midlayer2_maxwidth=0.13 midlayer2_prefwidth=0.13 midlayer3_maxgap=0.226 midlayer3_prefgap=0.226 midlayer3_minwidth=0.155 midlayer3_maxwidth=0.155 midlayer3_prefwidth=0.155 midlayer4_maxgap=0.226 midlayer4_prefgap=0.226 midlayer4_minwidth=0.155 midlayer4_maxwidth=0.155 midlayer4_prefwidth=0.155 bottomlayer_maxgap=0.226 bottomlayer_prefgap=0.226 bottomlayer_minwidth=0.155 bottomlayer_maxwidth=0.155 bottomlayer_prefwidth=0.155 maxuncoupledlength=12.7
DiffPairsRouting DiffPairs_USB_HS__90R [InDifferentialPairClass('PC_USB_HS_DIFF-90R')] p2: maxlimit=0.251 minlimit=0.226 mostfreqgap=0.251 toplayer_maxgap=0.226 toplayer_prefgap=0.226 toplayer_minwidth=0.155 toplayer_maxwidth=0.155 toplayer_prefwidth=0.155 midlayer1_maxgap=0.226 midlayer1_prefgap=0.226 midlayer1_minwidth=0.155 midlayer1_maxwidth=0.155 midlayer1_prefwidth=0.155 midlayer2_mingap=0.251 midlayer2_minwidth=0.13 midlayer2_maxwidth=0.13 midlayer2_prefwidth=0.13 midlayer3_maxgap=0.226 midlayer3_prefgap=0.226 midlayer3_minwidth=0.155 midlayer3_maxwidth=0.155 midlayer3_prefwidth=0.155 midlayer4_maxgap=0.226 midlayer4_prefgap=0.226 midlayer4_minwidth=0.155 midlayer4_maxwidth=0.155 midlayer4_prefwidth=0.155 bottomlayer_maxgap=0.226 bottomlayer_prefgap=0.226 bottomlayer_minwidth=0.155 bottomlayer_maxwidth=0.155 bottomlayer_prefwidth=0.155 maxuncoupledlength=12.7
DiffPairsRouting DiffPairs_USB_DEV_HS__90R [InDifferentialPairClass('PC_USB_DEV_HS_DIFF-90R')] p3: maxlimit=0.251 minlimit=0.226 mostfreqgap=0.251 toplayer_maxgap=0.226 toplayer_prefgap=0.226 toplayer_minwidth=0.155 toplayer_maxwidth=0.155 toplayer_prefwidth=0.155 midlayer1_maxgap=0.226 midlayer1_prefgap=0.226 midlayer1_minwidth=0.155 midlayer1_maxwidth=0.155 midlayer1_prefwidth=0.155 midlayer2_mingap=0.251 midlayer2_minwidth=0.13 midlayer2_maxwidth=0.13 midlayer2_prefwidth=0.13 midlayer3_maxgap=0.226 midlayer3_prefgap=0.226 midlayer3_minwidth=0.155 midlayer3_maxwidth=0.155 midlayer3_prefwidth=0.155 midlayer4_maxgap=0.226 midlayer4_prefgap=0.226 midlayer4_minwidth=0.155 midlayer4_maxwidth=0.155 midlayer4_prefwidth=0.155 bottomlayer_maxgap=0.226 bottomlayer_prefgap=0.226 bottomlayer_minwidth=0.155 bottomlayer_maxwidth=0.155 bottomlayer_prefwidth=0.155 maxuncoupledlength=12.7
DiffPairsRouting DiffPairs_USB_DEV_HS_CN__90R [InDifferentialPairClass('PC_USB_DEV_HS_CN_DIFF-90R')] p4: maxlimit=0.251 minlimit=0.226 mostfreqgap=0.251 toplayer_maxgap=0.226 toplayer_prefgap=0.226 toplayer_minwidth=0.155 toplayer_maxwidth=0.155 toplayer_prefwidth=0.155 midlayer1_maxgap=0.226 midlayer1_prefgap=0.226 midlayer1_minwidth=0.155 midlayer1_maxwidth=0.155 midlayer1_prefwidth=0.155 midlayer2_mingap=0.251 midlayer2_minwidth=0.13 midlayer2_maxwidth=0.13 midlayer2_prefwidth=0.13 midlayer3_maxgap=0.226 midlayer3_prefgap=0.226 midlayer3_minwidth=0.155 midlayer3_maxwidth=0.155 midlayer3_prefwidth=0.155 midlayer4_maxgap=0.226 midlayer4_prefgap=0.226 midlayer4_minwidth=0.155 midlayer4_maxwidth=0.155 midlayer4_prefwidth=0.155 bottomlayer_maxgap=0.226 bottomlayer_prefgap=0.226 bottomlayer_minwidth=0.155 bottomlayer_maxwidth=0.155 bottomlayer_prefwidth=0.155 maxuncoupledlength=12.7
HoleSize [All] p1: absolutevalues=TRUE maxlimit=10 minlimit=0.025 maxpercent=80.000 minpercent=20.000
MatchedLengths "Schematic Matched Net Lengths_3" [InNet('USB_DEV_HS_N')] p1: tolerance=0.2 checknetsindiffpair=TRUE checkdiffpairvsdiffpair=FALSE checkxsignals=FALSE checkothers=FALSE
MatchedLengths "Schematic Matched Net Lengths_2" [InNet('USB_DEV_HS_CN_P')] p2: tolerance=0.2 checknetsindiffpair=TRUE checkdiffpairvsdiffpair=FALSE checkxsignals=FALSE checkothers=FALSE
MatchedLengths "Schematic Matched Net Lengths_1" [InNet('USB_DEV_HS_CN_N')] p3: tolerance=0.2 checknetsindiffpair=TRUE checkdiffpairvsdiffpair=FALSE checkxsignals=FALSE checkothers=FALSE
MatchedLengths "Schematic Matched Net Lengths" [InNet('USB_DEV_HS_P')] p4: tolerance=0.2 checknetsindiffpair=TRUE checkdiffpairvsdiffpair=FALSE checkxsignals=FALSE checkothers=FALSE
MatchedLengths MatchedLengths_SDRAM [InNetClass('NC_SDRAM_SINGLE-55R')] p5: tolerance=7 checknetsindiffpair=FALSE checkdiffpairvsdiffpair=TRUE checkxsignals=TRUE checkothers=TRUE
MatchedLengths MatchedLengths_USB_HS_CN18__90R [InDifferentialPairClass('PC_USB_DEV_HS_CN18_DIFF-90R')] p6: tolerance=0.2 checknetsindiffpair=TRUE checkdiffpairvsdiffpair=FALSE checkxsignals=FALSE checkothers=FALSE
MatchedLengths MatchedLengths_USB_DEV_HS_CN__90R [InDifferentialPairClass('PC_USB_DEV_HS_CN_DIFF-90R')] p7: tolerance=0.2 checknetsindiffpair=TRUE checkdiffpairvsdiffpair=FALSE checkxsignals=FALSE checkothers=FALSE
MatchedLengths MatchedLengths_USB_HS__90R [InDifferentialPairClass('PC_USB_HS_DIFF-90R')] p8: tolerance=0.2 checknetsindiffpair=TRUE checkdiffpairvsdiffpair=FALSE checkxsignals=FALSE checkothers=FALSE
MatchedLengths MatchedLengths_USB_DEV_HS__90R [InDifferentialPairClass('PC_USB_DEV_HS_DIFF-90R')] p9: tolerance=0.2 checknetsindiffpair=TRUE checkdiffpairvsdiffpair=FALSE checkxsignals=FALSE checkothers=FALSE
MatchedLengths MatchedLengths_LCD [InNetClass('NC_LCD_SINGLE-55R')] p10: tolerance=14 checknetsindiffpair=FALSE checkdiffpairvsdiffpair=TRUE checkxsignals=TRUE checkothers=TRUE
MatchedLengths MatchedLengths_LCD-W127 [InNetClass('NC_LCD_SINGLE-55R_W127u')] p11: tolerance=14 checknetsindiffpair=FALSE checkdiffpairvsdiffpair=TRUE checkxsignals=TRUE checkothers=TRUE
MatchedLengths MatchedLengths_OCTO-SPI [InNetClass('NC_OCTO-SPI_SINGLE-55R')] p12: tolerance=7 checknetsindiffpair=FALSE checkdiffpairvsdiffpair=TRUE checkxsignals=TRUE checkothers=TRUE
MatchedLengths MatchedLengths_SD-CARD [InNetClass('NC_SD-CARD_SINGLE-55R')] p13: tolerance=7 checknetsindiffpair=FALSE checkdiffpairvsdiffpair=TRUE checkxsignals=TRUE checkothers=TRUE
MatchedLengths MatchedLengths_CAMERA [InNetClass('NC_CAMERA_SINGLE-55R')] p14: tolerance=14 checknetsindiffpair=FALSE checkdiffpairvsdiffpair=TRUE checkxsignals=TRUE checkothers=TRUE
MatchedLengths MatchedLengths_ULPI [InNetClass('NC_ULPI_SINGLE-55R')] p15: tolerance=14 checknetsindiffpair=FALSE checkdiffpairvsdiffpair=TRUE checkxsignals=TRUE checkothers=TRUE
MaxMinImpedance "Schematic Impedance Constraint" [InNet('USB_DEV_HS_P')] p1: minimum=85,00 maximum=95,00
MaxMinImpedance "Schematic Impedance Constraint_6" [InNet('USB_DEV_HS_N')] p2: minimum=85,00 maximum=95,00
MaxMinImpedance "Schematic Impedance Constraint_3" [InNet('USB_DEV_HS_CN_P')] p3: minimum=85,00 maximum=95,00
MaxMinImpedance "Schematic Impedance Constraint_2" [InNet('USB_DEV_HS_CN_N')] p4: minimum=85,00 maximum=95,00
MinimumSolderMaskSliver [All] p1: minsoldermaskwidth=0
PlaneConnect [All] p1: planeconnectstyle=Relief reliefexpansion=0.508 reliefentries=4 reliefconductorwidth=0.4 reliefairgap=0.4
PolygonConnect PolygonConnect_9 [All vs IsNamedPolygon('GND_L06_P020')] p1: connectstyle=Direct reliefconductorwidth=0.254 reliefentries=4 polygonreliefangle="90 Angle" airgapwidth=0.254
PolygonConnect PolygonConnect_8 [All vs IsNamedPolygon('GND_L06_P002')] p2: connectstyle=Direct reliefconductorwidth=0.254 reliefentries=4 polygonreliefangle="90 Angle" airgapwidth=0.254
PolygonConnect PolygonConnect_7 [All vs IsNamedPolygon('1V8_L06_P018')] p3: connectstyle=Direct reliefconductorwidth=0.254 reliefentries=4 polygonreliefangle="90 Angle" airgapwidth=0.254
PolygonConnect PolygonConnect_6 [All vs IsNamedPolygon('VCAP_L06_P014')] p4: connectstyle=Direct reliefconductorwidth=0.254 reliefentries=4 polygonreliefangle="90 Angle" airgapwidth=0.254
PolygonConnect PolygonConnect_5 [All vs IsNamedPolygon('VDD_LDO_L06_P016')] p5: connectstyle=Direct reliefconductorwidth=0.254 reliefentries=4 polygonreliefangle="90 Angle" airgapwidth=0.254
PolygonConnect PolygonConnect_4 [All vs IsNamedPolygon('VDD_SMPS_IND_OUT_L06_P012')] p6: connectstyle=Direct reliefconductorwidth=0.254 reliefentries=4 polygonreliefangle="90 Angle" airgapwidth=0.254
PolygonConnect PolygonConnect_3 [All vs IsNamedPolygon('GND_L06_P010')] p7: connectstyle=Direct reliefconductorwidth=0.254 reliefentries=4 polygonreliefangle="90 Angle" airgapwidth=0.254
PolygonConnect PolygonConnect_2 [All vs IsNamedPolygon('3V3_MCU_L06_P008')] p8: connectstyle=Direct reliefconductorwidth=0.254 reliefentries=4 polygonreliefangle="90 Angle" airgapwidth=0.254
PolygonConnect PolygonConnect_1 [All vs IsNamedPolygon('VDD_SMPS_OUT_L06_P006')] p9: connectstyle=Direct reliefconductorwidth=0.254 reliefentries=4 polygonreliefangle="90 Angle" airgapwidth=0.254
PolygonConnect [All vs IsNamedPolygon('3V3_SMPS_IN_L06_P004')] p10: connectstyle=Direct reliefconductorwidth=0.254 reliefentries=4 polygonreliefangle="90 Angle" airgapwidth=0.254
PolygonConnect PolygonConnect_Default [All] p11: thpad.connectstyle=Relief thpad.reliefconductorwidth=0.254 thpad.reliefentries=4 thpad.polygonreliefangle="45 Angle" thpad.airgapwidth=0.254 smdpad.connectstyle=Direct smdpad.reliefconductorwidth=0.254 smdpad.reliefentries=4 smdpad.polygonreliefangle="45 Angle" smdpad.airgapwidth=0.254 via.connectstyle=Direct via.reliefconductorwidth=0.254 via.reliefentries=4 via.polygonreliefangle="45 Angle" via.airgapwidth=0.254
RoomDefinition [InComponentClass('Room Definition 1') vs False] p1: confinementstyle=ConfineIn formatcopy=TRUE lockcomponents=FALSE outline 77.225,39.848 91.925,39.848 91.925,20.623 77.225,20.623
RoutingLayers RoutingLayers_SDRAM [InNetClass('NC_SDRAM_SINGLE-55R')] p1: top layer_v5=TRUE mid layer 1_v5=FALSE mid layer 2_v5=TRUE mid layer 3_v5=FALSE mid layer 4_v5=FALSE bottom layer_v5=TRUE
RoutingLayers RoutingLayers_USB_HS_CN18__90R [InDifferentialPairClass('PC_USB_DEV_HS_CN18_DIFF-90R')] p2: top layer_v5=TRUE mid layer 1_v5=FALSE mid layer 2_v5=TRUE mid layer 3_v5=FALSE mid layer 4_v5=FALSE bottom layer_v5=TRUE
RoutingLayers RoutingLayers_USB_DEV_HS_CN__90R [InDifferentialPairClass('PC_USB_DEV_HS_CN_DIFF-90R')] p3: top layer_v5=TRUE mid layer 1_v5=FALSE mid layer 2_v5=TRUE mid layer 3_v5=FALSE mid layer 4_v5=FALSE bottom layer_v5=TRUE
RoutingLayers RoutingLayers_USB_DEV_HS__90R [InDifferentialPairClass('PC_USB_DEV_HS_DIFF-90R')] p4: top layer_v5=TRUE mid layer 1_v5=FALSE mid layer 2_v5=TRUE mid layer 3_v5=FALSE mid layer 4_v5=FALSE bottom layer_v5=TRUE
RoutingLayers RoutingLayers_USB_HS__90R [InDifferentialPairClass('PC_USB_HS_DIFF-90R')] p5: top layer_v5=TRUE mid layer 1_v5=FALSE mid layer 2_v5=TRUE mid layer 3_v5=FALSE mid layer 4_v5=FALSE bottom layer_v5=TRUE
RoutingLayers RoutingLayers_LCD-W127 [InNetClass('NC_LCD_SINGLE-55R_W127u')] p6: top layer_v5=TRUE mid layer 1_v5=FALSE mid layer 2_v5=TRUE mid layer 3_v5=FALSE mid layer 4_v5=FALSE bottom layer_v5=TRUE
RoutingLayers RoutingLayers_LCD [InNetClass('NC_LCD_SINGLE-55R')] p7: top layer_v5=TRUE mid layer 1_v5=FALSE mid layer 2_v5=TRUE mid layer 3_v5=FALSE mid layer 4_v5=TRUE bottom layer_v5=TRUE
RoutingLayers RoutingLayers_OCTO-SPI [InNetClass('NC_OCTO-SPI_SINGLE-55R')] p8: top layer_v5=TRUE mid layer 1_v5=FALSE mid layer 2_v5=TRUE mid layer 3_v5=FALSE mid layer 4_v5=FALSE bottom layer_v5=TRUE
RoutingLayers RoutingLayers_SD-CARD [InNetClass('NC_SD-CARD_SINGLE-55R')] p9: top layer_v5=TRUE mid layer 1_v5=FALSE mid layer 2_v5=TRUE mid layer 3_v5=FALSE mid layer 4_v5=FALSE bottom layer_v5=TRUE
RoutingLayers RoutingLayers_CAMERA [InNetClass('NC_CAMERA_SINGLE-55R')] p10: top layer_v5=TRUE mid layer 1_v5=FALSE mid layer 2_v5=TRUE mid layer 3_v5=FALSE mid layer 4_v5=TRUE bottom layer_v5=TRUE
RoutingLayers RoutingLayers_ULPI [InNetClass('NC_ULPI_SINGLE-55R')] p11: top layer_v5=TRUE mid layer 1_v5=FALSE mid layer 2_v5=TRUE mid layer 3_v5=FALSE mid layer 4_v5=FALSE bottom layer_v5=TRUE
RoutingLayers RoutingLayers_Default [All] p12: top layer_v5=TRUE mid layer 1_v5=TRUE mid layer 2_v5=TRUE mid layer 3_v5=TRUE mid layer 4_v5=TRUE bottom layer_v5=TRUE
RoutingPriority RoutingPriority_ALL [All] p1: routingpriority=1
RoutingVias RoutingVias_Default [All] p1: holewidth=0.2 width=0.45 viastyle="Through Hole" minholewidth=0.2 minwidth=0.45 maxholewidth=0.2 maxwidth=0.45
SilkToSilkClearance [All] p1: silktosilkclearance=0
SilkToSolderMaskClearance [IsPad] p1: minsilkscreentomaskgap=0 clearancetoexposedcopper=TRUE
SolderMaskExpansion [All] p1: expansion=0.102 istentingtop=FALSE
Width Width_BGA-U24 [WithinRoom('RoomDefinition') And TouchesRoom('RoomDefinition')] p1: maxlimit=1 minlimit=0.1 preferedwidth=0.1 minimp=50.000000 maximp=50.000000 favimp=50.000000
Width Width_ALIMS_W2 [InNetClass('NC_ALIMS_W2mm')] p2: maxlimit=2 minlimit=0.1 preferedwidth=2
Width Width_ALIMS_W1 [InNetClass('NC_ALIMS_W1mm')] p3: maxlimit=1 minlimit=0.1 preferedwidth=1
Width Width_ALIMS_W0.8 [InNetClass('NC_ALIMS_W0.8mm')] p4: maxlimit=0.8 minlimit=0.1 preferedwidth=0.8
Width Width_ALIMS_W1.5 [InNetClass('NC_ALIMS_W1.5mm')] p5: maxlimit=1.5 minlimit=0.1 preferedwidth=1.5
Width Width_ALIMS_W0.5 [InNetClass('NC_ALIMS_W0.5mm')] p6: maxlimit=0.5 minlimit=0.1 preferedwidth=0.5
Width Width_ALIMS_W0.2 [InNetClass('NC_ALIMS_W0.2mm')] p7: maxlimit=0.8 minlimit=0.1 preferedwidth=0.2
Width Width_ALIMS_DEFAULT_W0.3 [InNetClass('NC_ALIMS_DEFAULT_W0.3mm')] p8: maxlimit=0.3 minlimit=0.1 preferedwidth=0.3
Width Width_GND [InNetClass('NC_GND')] p9: maxlimit=1 minlimit=0.1 preferedwidth=0.3 minimp=50.000000 maximp=50.000000 favimp=50.000000
Width Width_SDRAM [InNetClass('NC_SDRAM_SINGLE-55R')] p10: maxlimit=0.127 minlimit=0.1 preferedwidth=0.127 midlayer2_maxwidth=0.102 midlayer2_prefwidth=0.102 minimp=50.000000 maximp=50.000000 favimp=50.000000
Width Width_LCD-W127 [InNetClass('NC_LCD_SINGLE-55R_W127u')] p11: maxlimit=0.127 minlimit=0.1 preferedwidth=0.127 minimp=50.000000 maximp=50.000000 favimp=50.000000
Width Width_LCD [InNetClass('NC_LCD_SINGLE-55R')] p12: maxlimit=0.127 minlimit=0.1 preferedwidth=0.127 midlayer2_maxwidth=0.102 midlayer2_prefwidth=0.102 minimp=50.000000 maximp=50.000000 favimp=50.000000
Width Width_OCTO-SPI [InNetClass('NC_OCTO-SPI_SINGLE-55R')] p13: maxlimit=0.127 minlimit=0.1 preferedwidth=0.127 midlayer2_maxwidth=0.102 midlayer2_prefwidth=0.102 minimp=50.000000 maximp=50.000000 favimp=50.000000
Width Width_SD-CARD [InNetClass('NC_SD-CARD_SINGLE-55R')] p14: maxlimit=0.127 minlimit=0.1 preferedwidth=0.127 midlayer2_maxwidth=0.102 midlayer2_prefwidth=0.102 minimp=50.000000 maximp=50.000000 favimp=50.000000
Width Width_CAMERA [InNetClass('NC_CAMERA_SINGLE-55R')] p15: maxlimit=0.127 minlimit=0.1 preferedwidth=0.127 midlayer2_maxwidth=0.102 midlayer2_prefwidth=0.102 minimp=50.000000 maximp=50.000000 favimp=50.000000
Width Width_ULPI [InNetClass('NC_ULPI_SINGLE-55R')] p16: maxlimit=0.127 minlimit=0.1 preferedwidth=0.127 midlayer2_maxwidth=0.102 midlayer2_prefwidth=0.102 minimp=50.000000 maximp=50.000000 favimp=50.000000
Width Width_Default [All] p17: maxlimit=1 minlimit=0.1 preferedwidth=0.1 minimp=50.000000 maximp=50.000000 favimp=50.000000
21 further rules are at their usual default settings.

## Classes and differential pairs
net class NC_USB_DEV_HS_CN__90R: USB_DEV_HS_CN_N USB_DEV_HS_CN_P
net class NC_USB_DEV_HS__90R: USB_DEV_HS_N USB_DEV_HS_P
net class NC_USB_HS__90R: USB_HS_N USB_HS_P
net class NC_USB_HS_CN18__90R: USB_HS_CN18_N USB_HS_CN18_P
net class NC_LCD_SINGLE-55R_W127u: LCD_BL_CTRL LCD_INT LCD_ON/OFF
net class NC_LCD_SINGLE-55R: LCD_B0 LCD_B1 LCD_B2 LCD_B3 LCD_B4 LCD_B5 LCD_B6 LCD_B7 LCD_CLK LCD_DE LCD_G0 LCD_G1 LCD_G2 LCD_G3 LCD_G4 LCD_G5 LCD_G6 LCD_G7 LCD_HSYNC LCD_R0 LCD_R1 LCD_R2 LCD_R3 LCD_R4 LCD_R5 LCD_R6 LCD_R7 LCD_VSYNC
net class NC_OCTO-SPI_SINGLE-55R: NetR91_2 NetR92_1 NetR93_2 NetR94_1 NetR106_1 NetR107_2 NetR108_2 NetR109_1 NetR110_1 NetR111_2 NetR112_2 OCSPI1_CLK OCSPI1_DQS OCSPI1_IO0 OCSPI1_IO1 OCSPI1_IO2 OCSPI1_IO3 OCSPI1_IO4 OCSPI1_IO5 OCSPI1_IO6 OCSPI1_IO7 OCSPI1_NCS
net class NC_SD-CARD_SINGLE-55R: DCMI_D3 DCMI_D4 SDIO1_CK SDIO1_CMD SDIO1_D0 SDIO1_D2
net class NC_CAMERA_SINGLE-55R: DCMI_D0 DCMI_D1 DCMI_D2 DCMI_D3 DCMI_D4 DCMI_D5 DCMI_D6 DCMI_D7 DCMI_HSYNC DCMI_PIXCLK DCMI_PWR_EN DCMI_VSYNC
net class NC_ULPI_SINGLE-55R: ULPI_CK ULPI_D0 ULPI_D1 ULPI_D2 ULPI_D3 ULPI_D4 ULPI_D5 ULPI_D6 ULPI_D7 ULPI_DIR ULPI_NXT ULPI_STP
net class NC_SDRAM_SINGLE-55R: A0 A1 A2 A3 A4 A5 A6 A7 A8 A9 A10 A11 A14 A15 D0 D1 D2 D3 D4 D5 D6 D7 D8 D9 D10 D11 D12 D13 D14 D15 FMC_NBL0 FMC_NBL1 SDCKE1 SDCLK SDNCAS SDNE1 SDNRAS SDNWE
differential pair class PC_USB_DEV_HS_DIFF-90R: USB_DEV_HS
differential pair class PC_USB_DEV_HS_CN18_DIFF-90R: USB_HS_CN18
differential pair class PC_USB_HS_DIFF-90R: USB_HS
differential pair class PC_USB_DEV_HS_CN_DIFF-90R: USB_DEV_HS_CN
net class NC_ALIMS_W2mm: 5V
net class NC_ALIMS_W1mm: 5V_VIN E5V
net class NC_ALIMS_W0.8mm: 5V_USB_CHARGER 5V_USB_HS 5V_USB_STLK VIN
net class NC_ALIMS_W1.5mm: 3V3
net class NC_ALIMS_W0.5mm: 3V3_MCU 3V3_SMPS_IN 3V3_STLK
net class NC_ALIMS_W0.2mm: 1V8 1V8_LDO
net class NC_ALIMS_DEFAULT_W0.3mm: 3V3_VDDA 3V3_VREFP VBAT VCAP VDD50_USB VDD_LDO VDD_MMC VDD_SMPS_IND_OUT VDD_SMPS_OUT VFBSD VREGOUT33
net class NC_GND: GND GNDDetect
differential pair USB_DEV_HS_CN: +USB_DEV_HS_CN_P -USB_DEV_HS_CN_N
differential pair USB_DEV_HS: +USB_DEV_HS_P -USB_DEV_HS_N
differential pair USB_HS: +USB_HS_P -USB_HS_N
differential pair USB_HS_CN18: +USB_HS_CN18_P -USB_HS_CN18_N

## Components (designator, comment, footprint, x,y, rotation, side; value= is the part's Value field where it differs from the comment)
B1 "SW-PUSH-TS-02H-Black" SWI_JIUBABA_C-TS-02H-2-5-K-V-T_R_BLACK 5.9,62 r90 top
B2 "SW-PUSH-TS-02H-Blue" SWI_JIUBABA_C-TS-02H-2-5-B-V-T_R_BLUE 5.9,49.875 r90 top
C1 "Capacitor" C0402 65.25,71.3 r90 top value=100nF
C2 "Capacitor" C0402 67.2,63.85 r180 top value=100nF
C3 "Capacitor" C0805 67.2,62.525 r0 top value=10uF
C4 "Capacitor" C0402 51.65,37.9 r90 top value=100nF
C5 "Capacitor" C0805 13.749,34.272 r180 top value=10uF
C6 "Capacitor" C0402 55.325,36.525 r0 top value=100nF
C7 "Capacitor" C0402 55.325,35.725 r180 top value=100nF
C8 "Capacitor" C0805 13.774,31.972 r180 top value=10uF
C9 "Capacitor" C0402 55.325,34.95 r0 top value=100nF
C10 "Capacitor" C0402 84.075,33.873 r90 top value=100nF
C11 "Capacitor" C0402 55.325,34.125 r180 top value=100nF
C12 "Capacitor" C0402 55.325,33.325 r0 top value=100nF
C13 "Capacitor" C0402 84.075,32.173 r90 top value=100nF
C14 "Capacitor" C0603 55.275,30.975 r90 top value=4.7uF
C15 "Capacitor" C0402 79.075,30.798 r180 top value=100nF
C16 "Capacitor" C0402 72.075,30.348 r270 top value=100nF
C17 "Capacitor" C0402 79.075,29.898 r180 top value=100nF
C18 "Capacitor" C0402 80.3,28.923 r270 top value=100nF
C19 "Capacitor" C0402 50.625,29.2 r180 top value=100nF
C20 "Capacitor" C0402 74.425,28.398 r0 top value=100nF
C21 "Capacitor" C0402 96.075,27.248 r90 top value=100nF
C22 "Capacitor" C0402 74.425,27.498 r0 top value=100nF
C23 "Capacitor" C0402 90.075,27.473 r180 top value=100nF
C24 "Capacitor" C0402 147.825,26.65 r90 top value=100nF
C25 "Capacitor" C0402 148.65,26.65 r90 top value=100nF
C26 "Capacitor" C0402 90.075,26.448 r180 top value=1uF
C27 "Capacitor" C0402 84.275,25.198 r270 top value=100nF
C28 "Capacitor" C0402 85.125,25.198 r270 top value=100nF
C29 "Capacitor" C0402 90.075,25.548 r180 top value=100nF
C30 "Capacitor" C0402 96.55,25.373 r0 top value=100nF
C31 "Capacitor" C0402 145.275,24.725 r90 top value=100nF
C32 "Capacitor" C0402 141.3,24.625 r90 top value=100nF
C33 "Capacitor" C0402 143.375,24.625 r90 top value=100nF
C34 "Capacitor" C0402 140.075,24.475 r270 top value=100nF
C35 "Capacitor" C0402 81.625,23.598 r0 top value=100nF
C36 "Capacitor" C0402 139,23 r180 top value=100nF
C37 "Capacitor" C0402 86.325,22.923 r180 top value=1uF
C38 "Capacitor" C0402 88.375,22.923 r180 top value=100nF
C39 "Capacitor" C0402 86.325,22.023 r0 top value=100nF
C40 "Capacitor" C0402 88.375,22.023 r180 top value=100nF
C41 "Capacitor" C0402 139,21.775 r180 top value=100nF
C42 "Capacitor" C0402 139,21 r180 top value=100nF
C43 "Capacitor" C0402 148.3,20.525 r0 top value=100nF
C44 "Capacitor" C0603 145.65,19.8 r270 top value=2.2uF
C45 "Capacitor" C0402 120.225,20.275 r0 top value=100nF
C46 "Capacitor" C0603 92.025,19.573 r180 top value=4.7uF
C47 "Capacitor" C0402 139,19.75 r180 top value=100nF
C48 "Capacitor" C0402 148.3,19.75 r0 top value=100nF
C49 "Capacitor" C0402 148.3,19 r0 top value=100nF
C50 "Capacitor" C0603 141.225,17.85 r270 top value=2.2uF
C51 "Capacitor" C0402 92.025,18.448 r0 top value=100nF
C52 "Capacitor" C0603 136.575,17.95 r0 top value=4.7uF
C53 "Capacitor" C0402 88.675,17.723 r270 top value=100nF
C54 "Capacitor" C0402 145.675,17.8 r0 top value=100nF
C55 "Capacitor" C0603 136.575,16.7 r0 top value=1uF
C56 "Capacitor" C0402 142.675,16.075 r270 top value=100nF
C57 "Capacitor" C0402 143.425,16.075 r270 top value=100nF
C58 "Capacitor" C0402 144.625,16.075 r270 top value=100nF
C59 "Capacitor" C0402 116.85,14.125 r90 top value=100nF
C60 "Capacitor" C0402 102.075,11.9 r270 top value=100nF
C61 "Capacitor" C0402 107.35,10.925 r90 top value=100nF
C62 "Capacitor" C0402 104.325,6.825 r180 top value=100nF
C63 "Capacitor" C0402 95.15,67.4 r90 bottom value=100nF
C64 "Capacitor" C0603 96.3,67.075 r90 bottom value=10uF
C65 "Capacitor" C0603 37.125,64.075 r180 bottom value=22nF
C66 "Capacitor" C0603 59.575,57.125 r270 bottom value=4.7uF
C67 "Capacitor" C0603 45.875,57 r0 bottom value=22nF
C68 "Capacitor" C0402 38.95,55.45 r270 bottom value=1.8nF
C69 "Capacitor" C0402 37.6,55.825 r0 bottom value=1uF
C70 "Capacitor" C0402 38.95,53.675 r270 bottom value=1.8nF
C71 "Capacitor" C0402 37.6,53.225 r0 bottom value=1uF
C72 "Capacitor" C0402 43.35,51.575 r90 bottom value=100nF
C73 "Capacitor" C0402 39.2,51.175 r270 bottom value=150pF
C74 "Capacitor" C0402 38.3,51.175 r270 bottom value=150pF
C75 "Capacitor" C0402 37.2,51.175 r90 bottom value=100nF
C76 "Capacitor" C0402 44.425,49.8 r180 bottom value=1uF
C77 "Capacitor" C0603 33.25,49.375 r0 bottom value=10uF
C78 "Capacitor" C0402 44.425,48.9 r180 bottom value=100nF
C79 "Capacitor" C0402 95.6,48.375 r270 bottom value=100nF
C80 "Capacitor" C0402 33.575,48.275 r180 bottom value=1uF
C81 "Capacitor" C0402 33.575,47.4 r180 bottom value=1uF
C82 "Capacitor" C0402 33.575,46.5 r180 bottom value=1uF
C83 "Capacitor" C0402 33.575,45.625 r0 bottom value=100nF
C84 "Capacitor" C0402 33.575,44.725 r180 bottom value=1uF
C85 "Capacitor" C0402 75.2,43.173 r180 bottom value=100nF
C86 "Capacitor" C0402 78.875,42.723 r270 bottom value=100nF
C87 "Capacitor" C0402 35.6,42.6 r180 bottom value=1uF
C88 "Capacitor" C0402 36.9,42.2 r90 bottom value=100nF
C89 "Capacitor" C0603 81.075,41.698 r0 bottom value=1uF
C90 "Capacitor" C0402 93.2,39.5 r180 bottom value=100nF
C91 "Capacitor" C0402 95.125,37.048 r270 bottom value=1.5pF
C92 "Capacitor" C0402 20.6,36.175 r270 bottom value=1uF
C93 "Capacitor" C0603 24.8,35.925 r0 bottom value=4.7uF
C94 "Capacitor" C0402 18.25,35.7 r0 bottom value=10nF
C95 "Capacitor" C0402 95.125,35.298 r90 bottom value=1.5pF
C96 "Capacitor" C0603 28.625,34.575 r180 bottom value=4.7uF
C97 "Capacitor" C0603 100.525,32.648 r90 bottom value=4.7uF
C98 "Capacitor" C0603 97.45,32.623 r270 bottom value=10uF
C99 "Capacitor" C0402 94,32.548 r180 bottom value=100pF
C100 "Capacitor" C0402 26,30.85 r0 bottom value=100nF
C101 "Capacitor" C0402 20.15,30.375 r0 bottom value=1uF
C102 "Capacitor" C0402 18.3,30.375 r180 bottom value=100nF
C103 "Capacitor" C0402 95.125,29.373 r180 bottom value=10uF
C104 "Capacitor" C0402 143.625,28.925 r180 bottom value=100nF
C105 "Capacitor" C0402 95.125,28.473 r180 bottom value=10uF
C106 "Capacitor" C0402 136.9,28.05 r90 bottom value=100nF
C107 "Capacitor" C0402 95.125,24.448 r270 bottom value=2.7pF
C108 "Capacitor" C0402 24.075,23.2 r90 bottom value=100nF
C109 "Capacitor" C0402 126.925,23.2 r180 bottom value=10nF
C110 "Capacitor" C0402 95.125,22.698 r90 bottom value=2.7pF
C111 "Capacitor" C0402 25.65,23.025 r0 bottom value=100nF
C112 "Capacitor" C0603 120.175,22.075 r270 bottom value=1uF
C113 "Capacitor" C0402 121.4,21.75 r90 bottom value=100nF
C114 "Capacitor" C0402 154.15,21.775 r0 bottom value=100pF
C115 "Capacitor" C0603 126.675,20.6 r90 bottom value=1uF
C116 "Capacitor" C0402 127.825,20.85 r270 bottom value=100nF
C117 "Capacitor" C0402 18.7,18.875 r180 bottom value=100nF
C118 "Capacitor" C0402 18.7,18 r180 bottom value=100nF
C119 "Capacitor" C0402 129.075,17.4 r0 bottom value=100nF
C120 "Capacitor" C0603 18.375,16.85 r0 bottom value=2.2uF
C121 "Capacitor" C0603 127.125,14.625 r270 bottom value=1uF
C122 "Capacitor" C0402 141.225,13.95 r270 bottom value=20pF
C123 "Capacitor" C0603 144.5,13.625 r90 bottom value=2.2uF
C124 "Cap_POL_TANA" CPOL_TAJ-A_1206_H180 15.7,9.975 r0 bottom value=4.7uF
CN1 "Header 25x2" MOD_LCD_MB1046B__CON_SAMTEC_FLE-125-01-G-DV 80.5,75 r0 top locked
CN2 "Header 2x1" CON_SAMTEC_TSW-102-07-G-S 10.5,60.375 r90 top
CN3 "Socket 10x2" MOD_MICRO_MB1299_CON_FCI_20021311-XXX20XXLF 153.94,50.11 r270 top value=20021311-00020T4LF
CN4 "microSD-PJS008-2003" CON_MICROSD_YAMAICHI_PJS008-2003-1 58.725,75 r90 bottom value=PJS008-2003-1
CN5 "Jack_PJ3028B-3_3P" CON_PHONE-JACK-3P5_HY_PJ3028B 42.45,75 r270 bottom value=PJ3028B-3_GR
CN6 "Jack_PJ3028B-3_3P" CON_PHONE-JACK-3P5_HY_PJ3028B 29.725,75 r270 bottom value=PJ3028B-3_BE
CN7 "FPU330ZH-BT1D3-CA" CON_TOWNES_FPU330ZH-BT1D3-CA_P050 87.904,72.025 r0 bottom
CN8 "Header 7x2" CON_STDC14_Receiver_MEDIUM_WITH_MIPI10_3D 17.1,67.282 r0 bottom value="MIPI10 on STDC14 footprint"
CN9 "Header 2x1" CON_988-JIUBABA_PHFS25-11-02-G0B115-T-1 16.3,57.775 r180 bottom value="header 2x1"
CN10 "Socket 10x1" CON_FISCHER_BL1-10-G 89.234,52.6 r0 bottom locked value="BL 1-10 G"
CN11 "Socket 8x1" CON_FISCHER_BL1-8-G 64.85,52.6 r0 bottom locked value="BL 1-8 G"
CN12 "Tag-10-C" CON_TAG-C_TC2050-IDC-NL 7.25,39.36 r180 top value=TC2050-IDC-NL
CN13 "Header 2x1" CON_SAMTEC_TSW-102-07-G-S 143.7,31.15 r0 bottom
CN14 "USB_uB_105017.0001" CON_USBMICROB_MOLEX_105017-0001_H2P90 161,17.7 r270 bottom value=USB_uB_105017-0001
CN15 "USB_uAB_47590.0001" CON_USBMICROAB_MOLEX_47590-0001_H3 0,16.15 r90 bottom value="USB uAB ZX62RD-AB-5P8(30)"
CN16 "Socket 4x2" CON_SAMTEC_SSM-104-L-DH 41.7,7.95 r180 bottom value=SSM-104-L-DH
CN17 "Header 4x1" CON_SAMTEC_TSW-104-07-G-S 148.75,8.12 r90 bottom
CN18 "Header 2x1" CON_SAMTEC_TSW-102-07-G-S 120.475,9.8 r180 bottom
CN19 "Socket 8x1" CON_FISCHER_BL1-8-G 82.63,4.34 r180 bottom locked value="BL 1-8 G"
CN20 "Socket 6x1" CON_FISCHER_BL1-6-G 62.31,4.34 r180 bottom locked value="BL 1-6 G"
CN21 "Header 2x1" CON_SAMTEC_TSW-102-07-G-S 120.475,3.35 r0 bottom
D1 "BAT60JFILM" DIO_SOD323 116.93,25.775 r0 bottom
D2 "BAT60JFILM" DIO_SOD323 116.93,23.85 r0 bottom
D3 "BAT60JFILM" DIO_SOD323 116.93,21.9 r0 bottom
D4 "ESD-TRANSIL" ESD_QFN2_1P6X1_P125 154.125,20.45 r180 bottom value=ESDA7P60-1U1M
Designator1 "Comment" MIRE_PLACE_SMD_0P8MM 149.3,68.1 r180 top
Designator2 "Comment" MIRE_PLACE_SMD_0P8MM 155.9,11.125 r180 top
Designator3 "Comment" MIRE_PLACE_SMD_0P8MM 11.975,4.625 r180 top
Designator4 "Comment" MIRE_PLACE_SMD_0P8MM 10.075,67.7 r0 bottom
Designator5 "Comment" MIRE_PLACE_SMD_0P8MM 156.775,62.9 r0 bottom
Designator6 "Comment" MIRE_PLACE_SMD_0P8MM 10.225,2.875 r0 bottom
Designator20 "Comment" LOGO_ETIQUETTE 133.45,62.05 r270 top
Designator21 "Comment" LOGO_ETIQUETTE 94.275,55.275 r180 bottom
H1 "POSITION HOLE C6D3R5" PTH_M1261-3005-N_3P5X6_M3_H14 156,70 r0 bottom locked
H2 "POSITION HOLE C6D3R5" PTH_M1261-3005-N_3P5X6_M3_H14 5,70 r0 bottom locked
H3 "POSITION HOLE C6D3R5" PTH_M1261-3005-N_3P5X6_M3_H14 156,5 r0 bottom locked
H4 "POSITION HOLE C6D3R5" PTH_M1261-3005-N_3P5X6_M3_H14 5,5 r0 bottom locked
JP1 "Jumper_Header 5x2 Fitted 1-2" CON_SAMTEC_TSM-105-01-L-DV 7.15,50.265 r270 bottom value="Header 5x2"
JP2 "Jumper_Header 2x1" CON_SAMTEC_TSW-102-07-G-S 28.1,40.775 r0 bottom value="Shunt not fitted"
L1 "Inductor" L0805_H0P9 94.3,31.098 r0 bottom value="2.2uH, 1.2A"
LD1 "LED_green" LED_0603_VISHAY_VLMTG1300-GS08_GREEN_1A2K_H0P8 56.975,66.775 r180 top value=GREEN
LD2 "LED_blue" LED_0603_OSRAM_LB-Q39G-L2OO-35-1_BLUE_1A2K_H0P4 4.3,57.325 r0 top value=BLUE
LD3 "LED_red" LED_0603_VISHAY_VLMS1300-GS08_RED_1A2K_H0P8 4.3,55.475 r0 top value=RED
LD4 "LD_BICOLOR_CMS" LED_BI-GR_HSMF-A201-A00J1 152.475,30.275 r180 top
LD5 "LED_green" LED_0603_VISHAY_VLMTG1300-GS08_GREEN_1A2K_H0P8 8.425,43.025 r0 bottom value="TRUE GREEN"
LD6 "LED_green" LED_0603_VISHAY_VLMTG1300-GS08_GREEN_1A2K_H0P8 12.25,21.925 r0 bottom value=GREEN
LD7 "LED_red" LED_0603_VISHAY_VLMS1300-GS08_RED_1A2K_H0P8 133.875,16.425 r90 bottom value=RED
LD8 "LED_red" LED_0603_VISHAY_VLMS1300-GS08_RED_1A2K_H0P8 12.175,13.9 r0 bottom value=RED
P1 "Socket 10X2 STMod+" CON_SAMTEC_SQT-110-01-F-D-RA__STMOD+ 109.82,66.49 r180 top
Q1 "BSN20" MOS_SOT23 57.325,63.65 r90 top value=BSN20BK
R1 "Resistor" R0402 59.325,66.775 r0 top value=330R
R2 "Resistor" R0603 66.35,60.325 r90 top value=0R
R3 "Resistor" R0603 68.05,60.325 r90 top value=0R
R4 "Resistor" R0603 7.175,57.325 r0 top value=680R
R5 "Resistor" R0402 55.65,56.075 r90 top value=47K
R6 "Resistor" R0402 56.6,56.075 r90 top value=47K
R7 "Resistor" R0402 60.95,56.05 r90 top value=47K
R8 "Resistor" R0402 62.95,56.05 r90 top value=47K
R9 "Resistor" R0402 64.025,56.05 r90 top value=47K
R10 "Resistor" R0603 7.175,55.475 r0 top value=680R
R11 "Resistor" R0402 8.875,50.4 r180 top value=100K
R12 "Resistor" R0402 87.075,35.023 r0 top value=0R
R13 "Resistor" R0402 87.075,33.973 r0 top value=0R
R14 "Resistor" R0402 91.4,32.398 r180 top value=0R
R15 "Resistor" R0402 9.5,27.7 r180 top value=10K
R16 "Resistor" R0603 151.725,26.5 r270 top value=330R
R17 "Resistor" R0603 153.225,26.5 r270 top value=330R
R18 "Resistor" R0603 86.65,19.573 r0 top value=0R
R19 "Resistor" R0603 86.65,18.173 r180 top value=0R
R20 "Resistor" R0402 123.9,14.125 r90 top value=10K
R21 "Resistor" R0402 119.45,6.625 r180 top value=120R
R22 "Resistor" R0603 22.15,72.4 r90 bottom value=22R
R23 "Resistor" R0402 19.65,72.05 r270 bottom value=100R
R24 "Resistor" R0603 68.925,69.525 r0 bottom value=10K
R25 "Resistor" R0402 91.725,67.325 r90 bottom value=51R
R26 "Resistor" R0402 90.65,67.325 r90 bottom value=51R
R27 "Resistor" R0603 37.125,62.6 r180 bottom value=49.9R
R28 "Resistor" R0603 22.15,61.9 r270 bottom value=22R
R29 "Resistor" R0603 19.125,62.3 r0 bottom value=22R
R30 "Resistor" R0603 13.875,62.3 r180 bottom value=22R
R31 "Resistor" R0603 19.125,60.6 r0 bottom value=22R
R32 "Resistor" R0603 13.875,60.6 r180 bottom value=22R
R33 "Resistor" R0402 35.8,55.825 r0 bottom value=100R
R34 "Resistor" R0402 34.05,55.825 r180 bottom value=100K
R35 "Resistor" R0603 45.875,55.6 r180 bottom value=49.9R
R36 "Resistor" R0603 7.725,44.2 r90 top value=22R
R37 "Resistor" R0603 13.95,51.2 r0 top value=22R
R38 "Resistor" R0603 13.95,45.725 r0 top value=22R
R39 "Resistor" R0603 13.95,47.1 r0 top value=22R
R40 "Resistor" R0603 13.95,48.475 r0 top value=22R
R41 "Resistor" R0603 13.95,49.825 r0 top value=22R
R42 "Resistor" R0402 35.8,53.225 r0 bottom value=100R
R43 "Resistor" R0402 34.05,53.225 r0 bottom value=100K
R44 "Resistor" R0402 40.875,51.175 r270 bottom value=10K
R45 "Resistor" R0402 95.6,50.075 r270 bottom value=0R
R46 "Resistor" R0402 44.425,47.925 r0 bottom value=0R
R47 "Resistor" R0402 44.425,46.875 r0 bottom value=0R
R48 "Resistor" R0402 44.425,45.8 r0 bottom value=0R
R49 "Resistor" R0402 44.425,44.725 r0 bottom value=0R
R50 "Resistor" R0402 44.425,43.65 r0 bottom value=0R
R51 "Resistor" R0402 93.3,42.648 r180 bottom value=10K
R52 "Resistor" R0402 44.425,42.6 r0 bottom value=0R
R53 "Resistor" R0402 42.15,42.2 r270 bottom value=0R
R54 "Resistor" R0402 41.1,42.2 r270 bottom value=0R
R55 "Resistor" R0402 40.025,42.2 r270 bottom value=1K5
R56 "Resistor" R0402 38.95,42.2 r270 bottom value=1K5
R57 "Resistor" R0402 37.9,42.2 r270 bottom value=10K
R58 "Resistor" R0402 93.3,41.598 r180 bottom value=10K
R59 "Resistor" R0402 44.429,41.583 r0 bottom value=0R
R60 "Resistor" R0402 44.429,40.523 r0 bottom value=0R
R61 "Resistor" R0603 5.475,43.025 r0 bottom value=820R
R62 "Resistor" R0402 93.825,36.698 r180 bottom value=0R
R63 "Resistor" R0402 93.825,35.648 r180 bottom value=0R
R64 "Resistor" R0402 27.925,32.425 r270 bottom value=10K
R65 "Resistor" R0402 18.3,29.075 r0 bottom value=10K
R66 "Resistor" R0402 137.9,28.05 r90 bottom value=10K
R67 "Resistor" R0603 55.925,27.05 r270 bottom value=0R
R68 "Resistor" R0402 144.85,27.35 r270 bottom value=100R
R69 "Resistor" R0402 145.925,27.35 r270 bottom value=10K
R70 "Resistor" R0402 142.55,27.5 r0 bottom value=100R
R71 "Resistor" R0603 95.375,27.323 r180 bottom value=0R
R72 "Resistor" R0603 25.975,24.275 r180 bottom value=0R
R73 "Resistor" R0402 150.55,24.275 r0 bottom value=4K7
R74 "Resistor" R0402 93.825,24.098 r180 bottom value=0R
R75 "Resistor" R0402 23.05,23.2 r90 bottom value=4K7
R76 "Resistor" R0402 21.975,23.2 r270 bottom value=100K
R77 "Resistor" R0402 150.55,23.225 r0 bottom value=4K7
R78 "Resistor" R0402 93.825,23.048 r180 bottom value=0R
R79 "Resistor" R0402 150.55,22.15 r180 bottom value=2K7
R80 "Resistor" R0603 9.675,21.925 r180 bottom value=330R
R81 "Resistor" R0603 18.375,21.375 r180 bottom value=8K06
R82 "Resistor" R0402 150.55,21.1 r180 bottom value=4K7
